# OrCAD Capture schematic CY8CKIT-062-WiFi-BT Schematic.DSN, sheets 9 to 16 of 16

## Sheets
9 10. PSoC 6 Signals: size A4
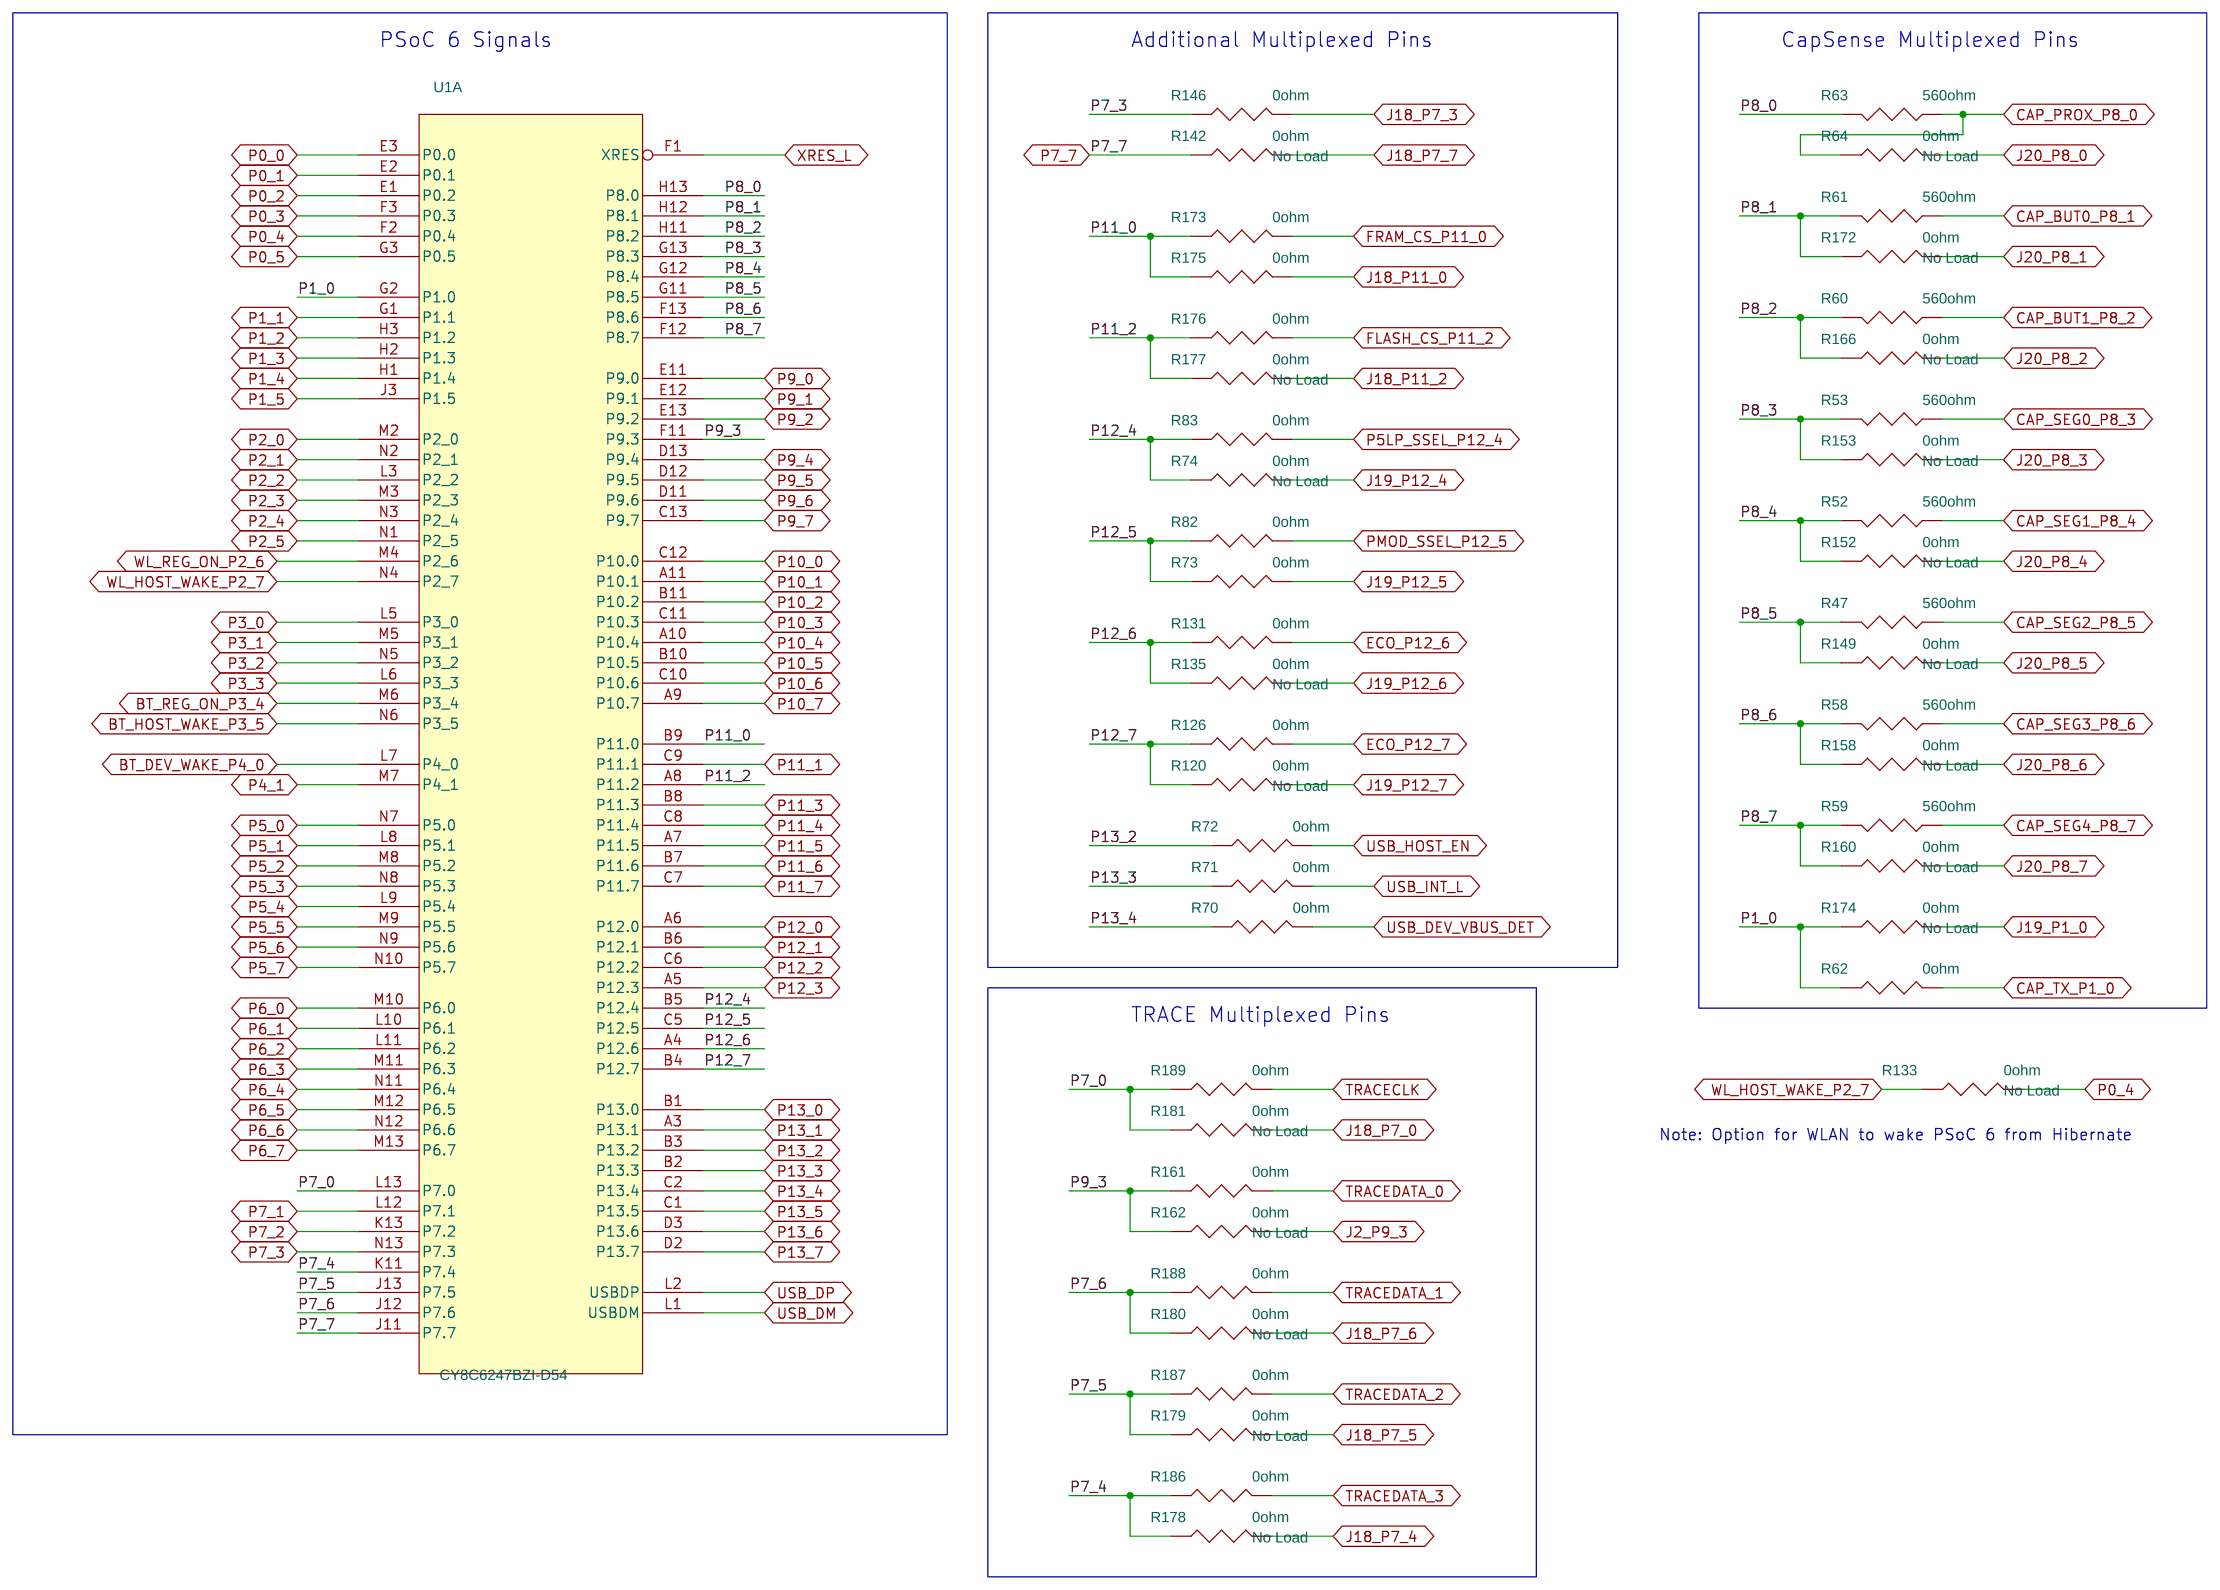
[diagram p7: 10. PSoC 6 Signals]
10 11. On-board Peripherals: size A4
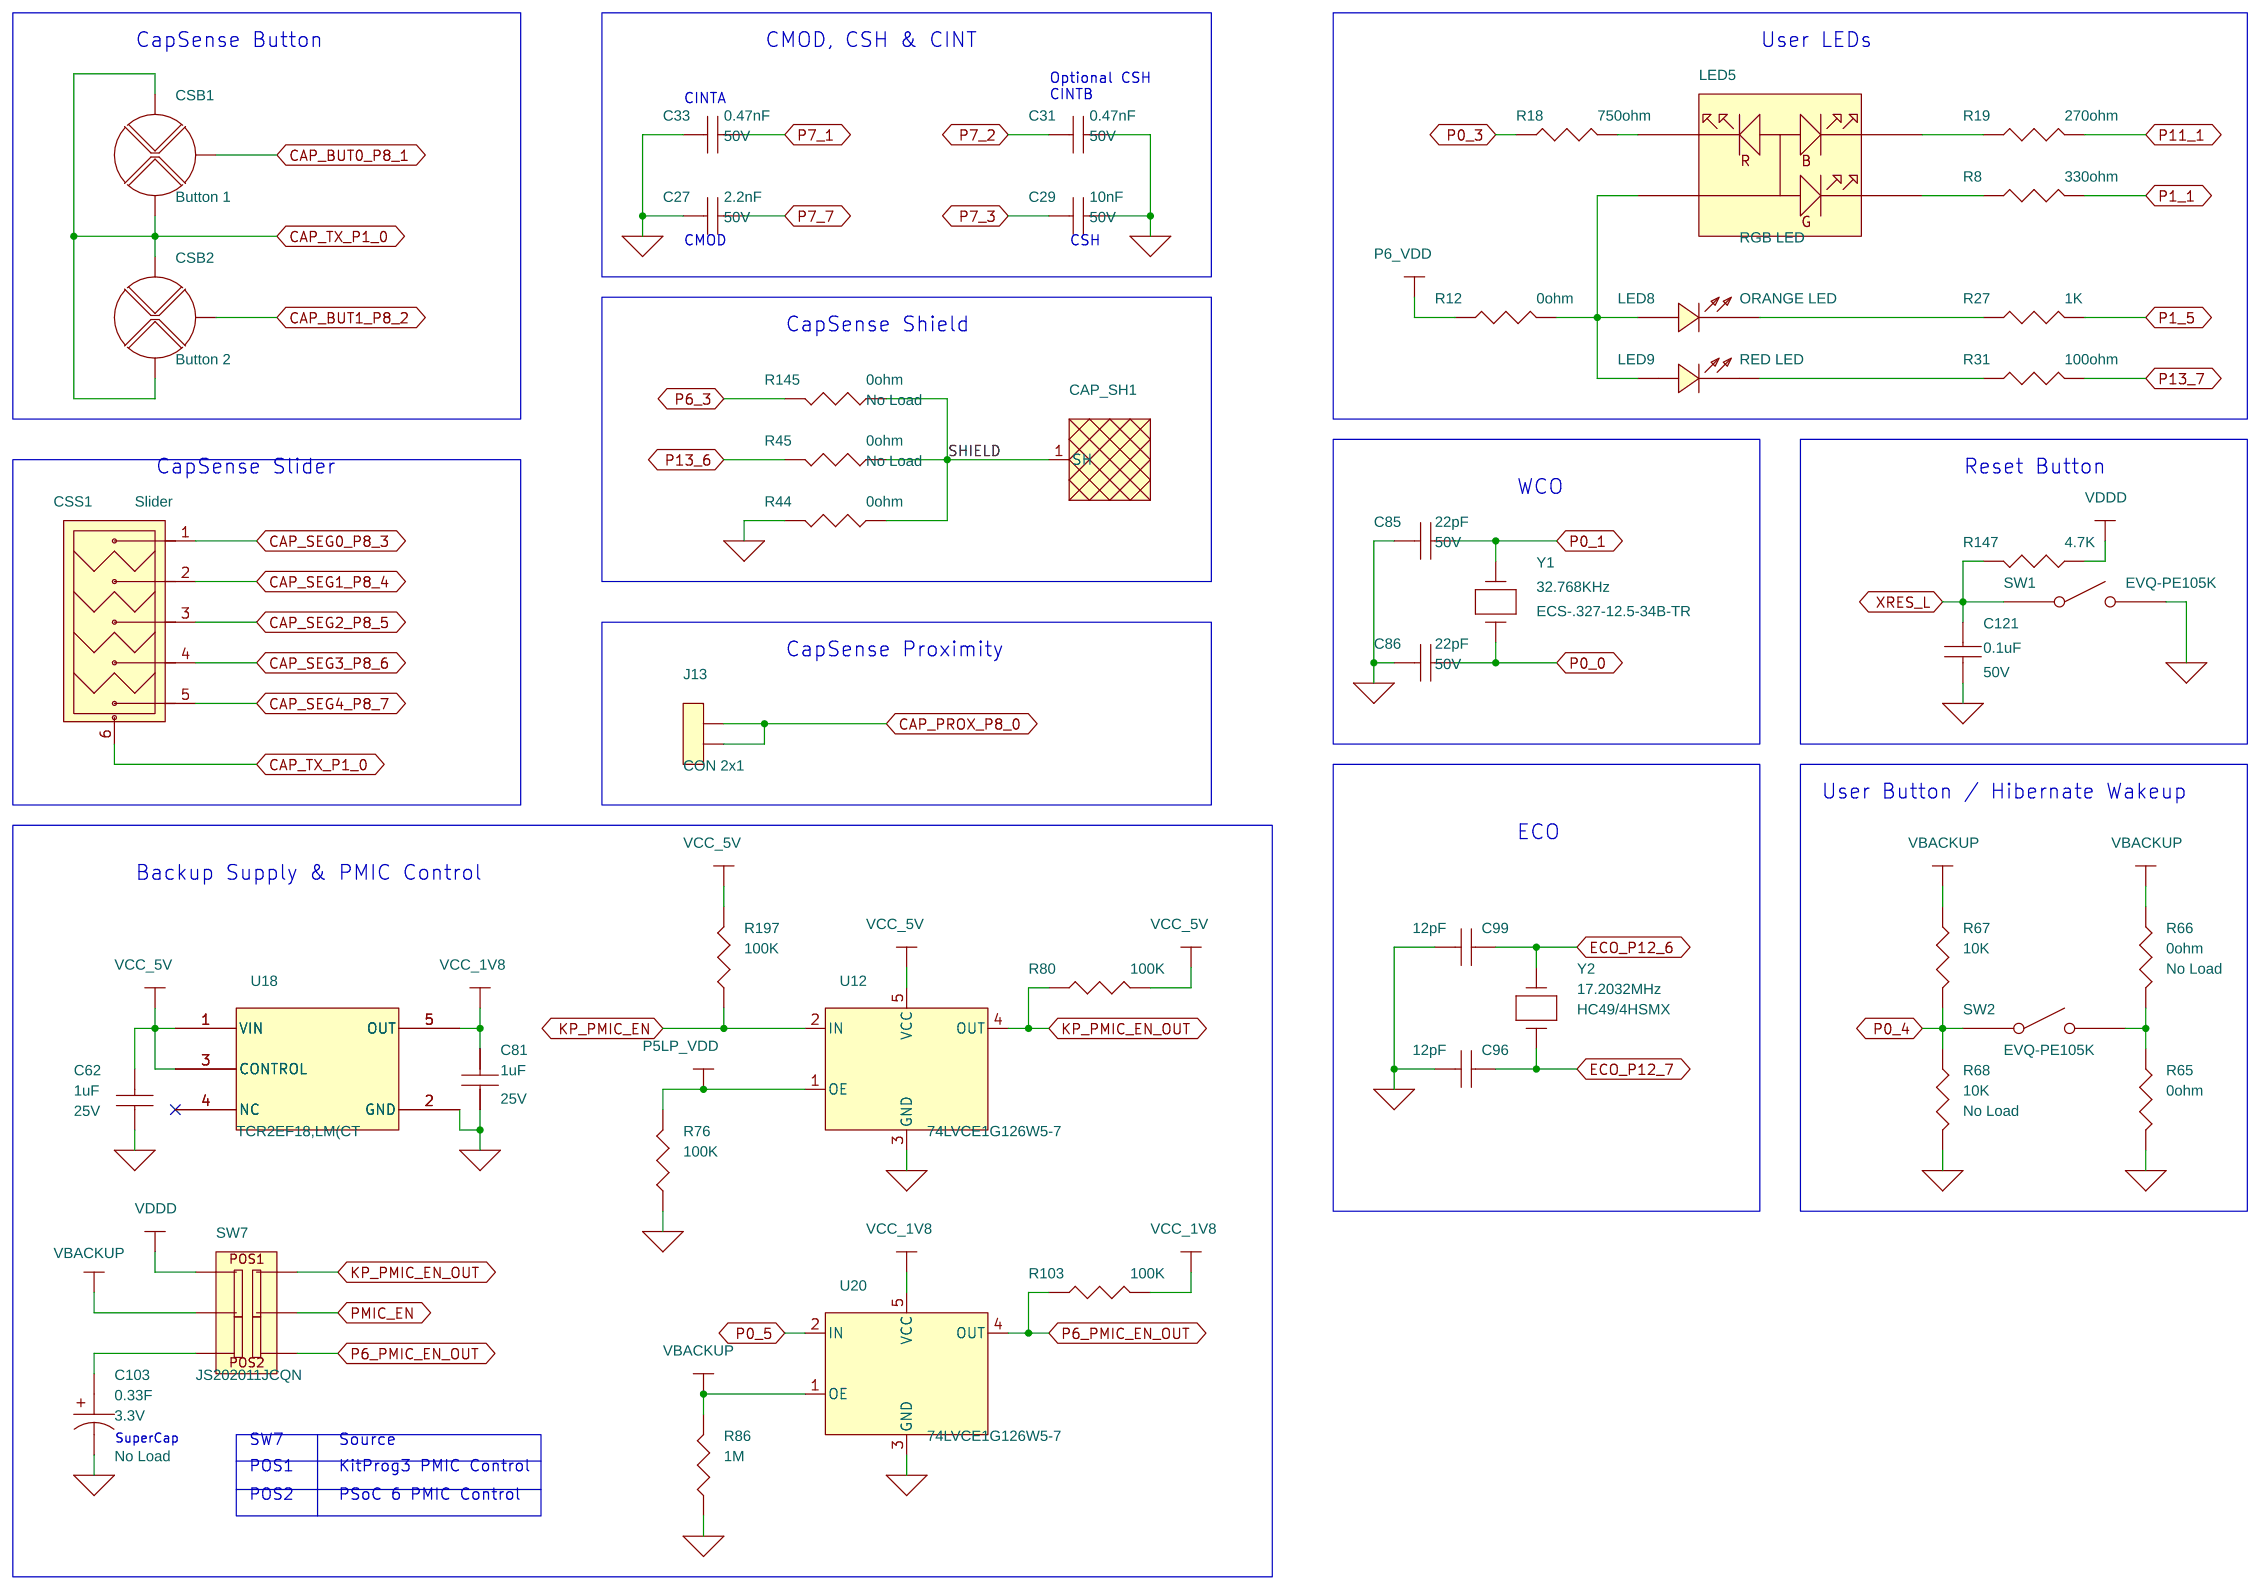
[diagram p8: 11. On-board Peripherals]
11 12. Expansion headers & memory: size A4
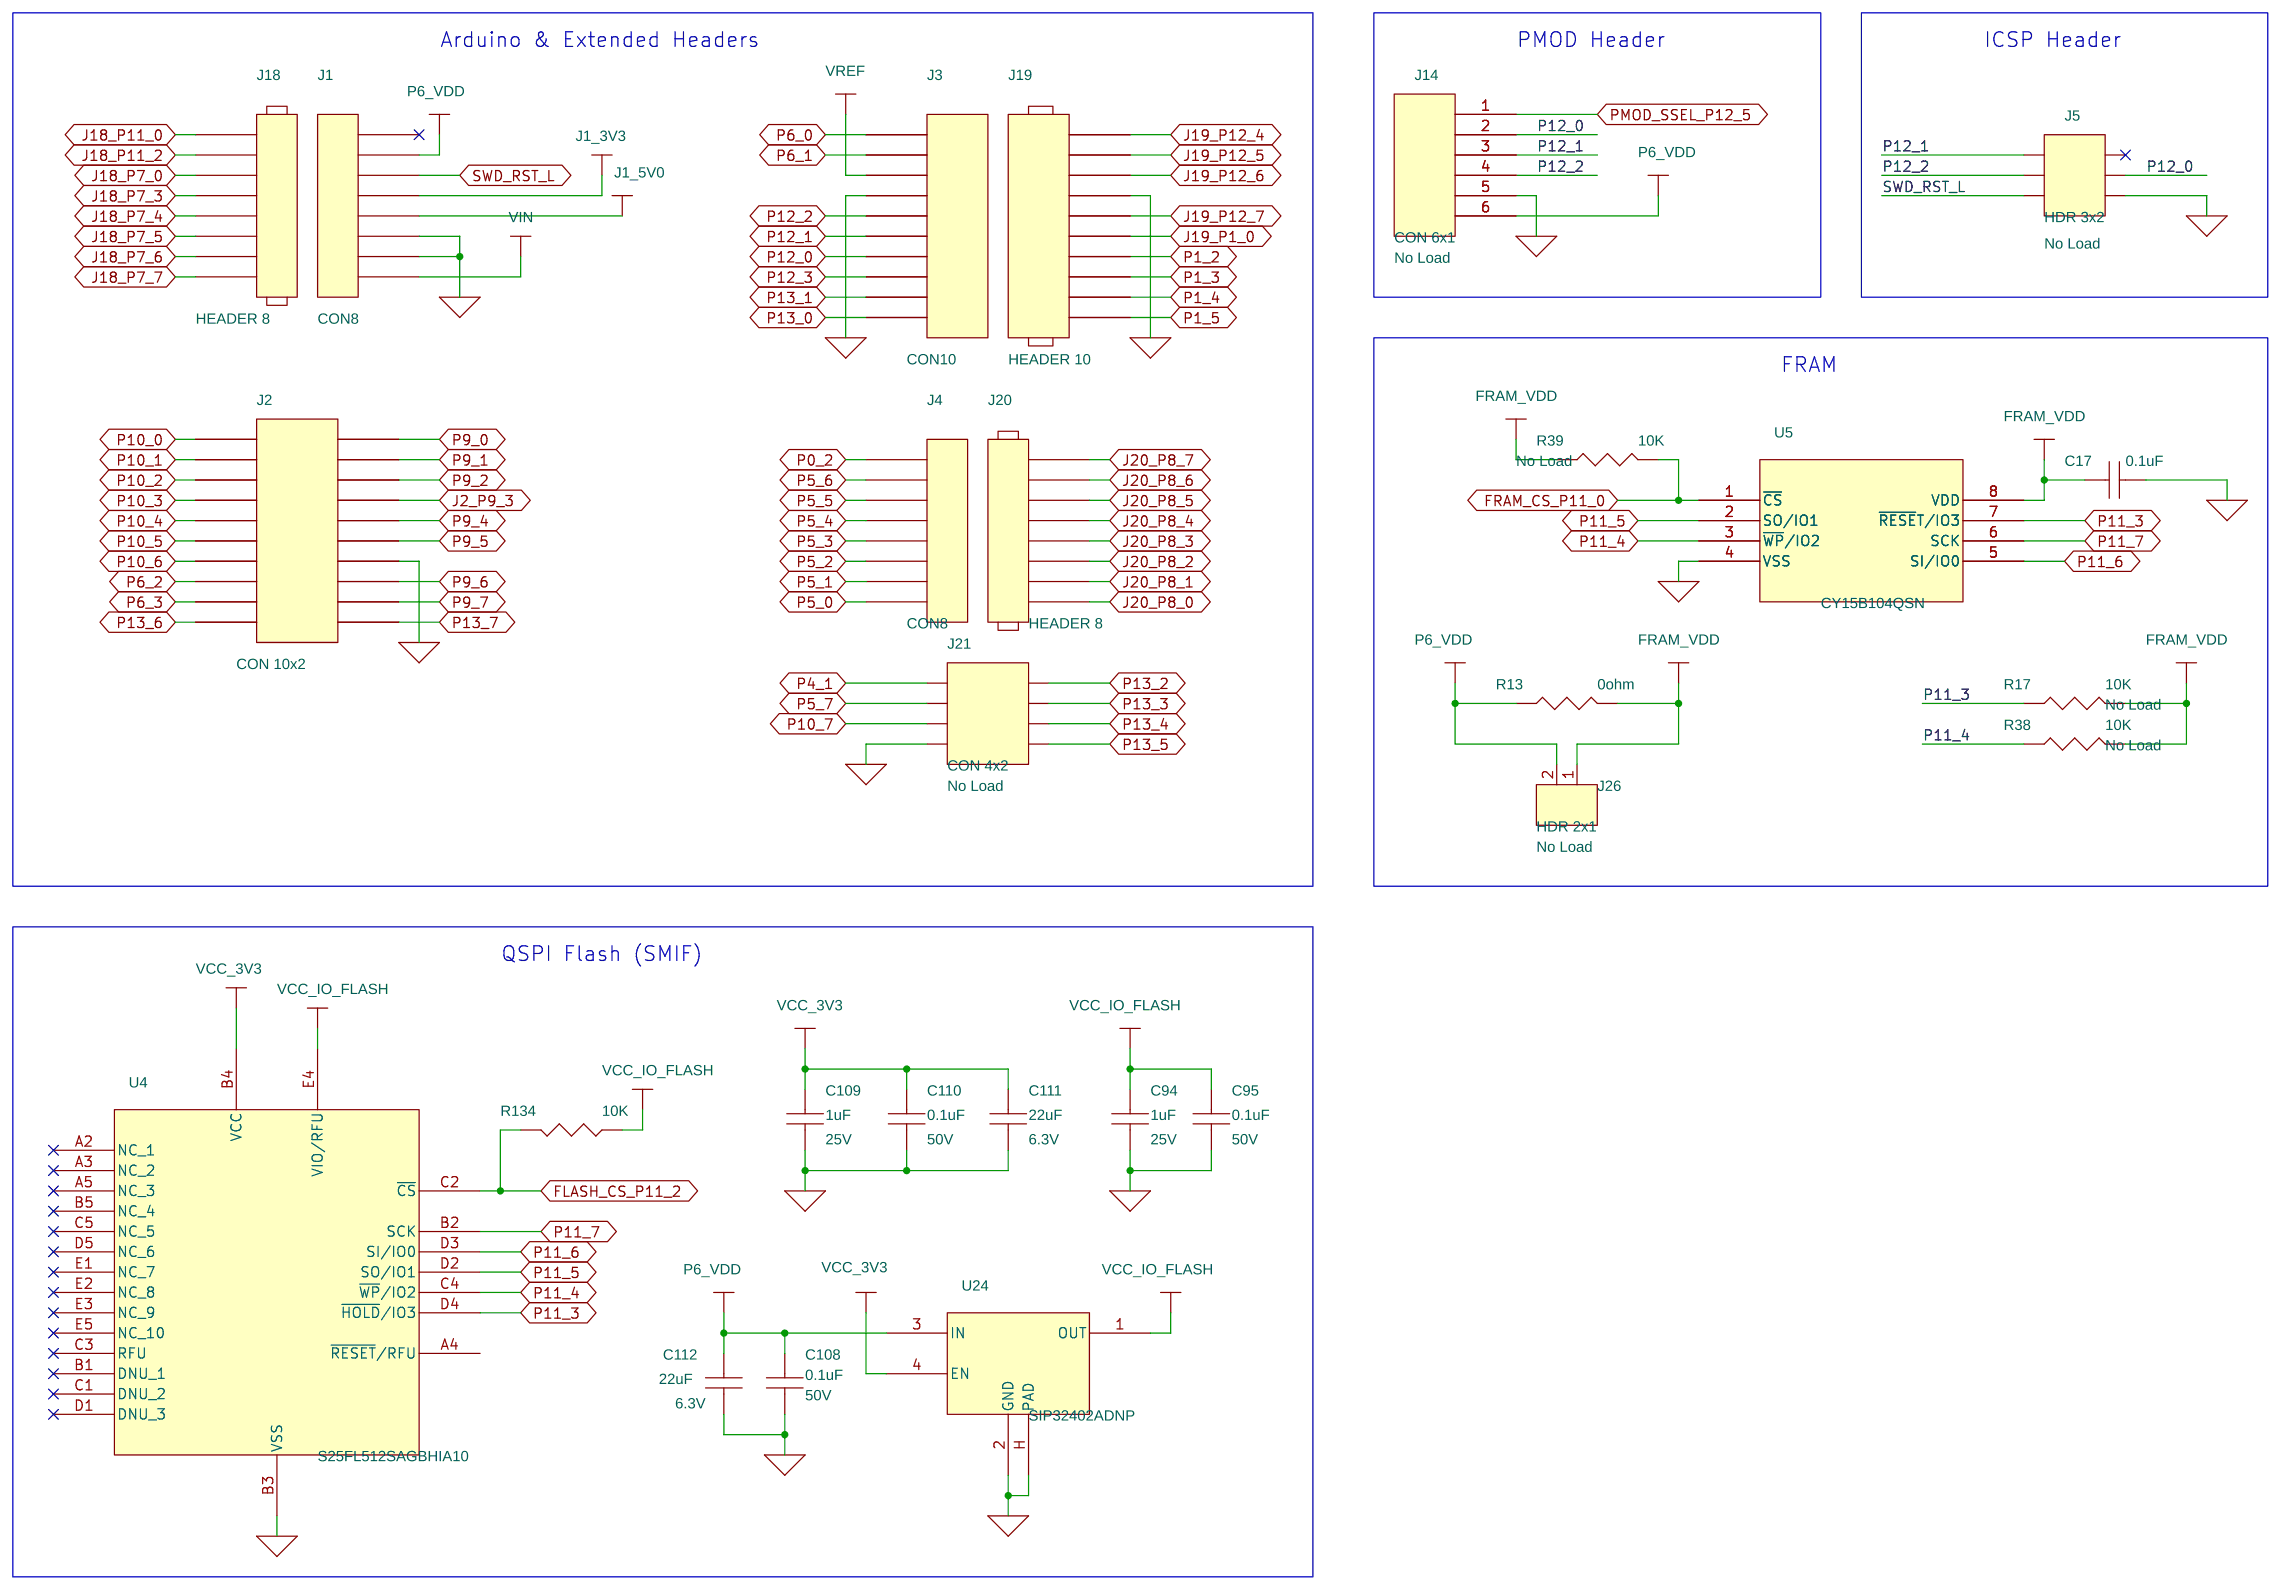
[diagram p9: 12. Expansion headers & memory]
12 13. USB host and device: size A4
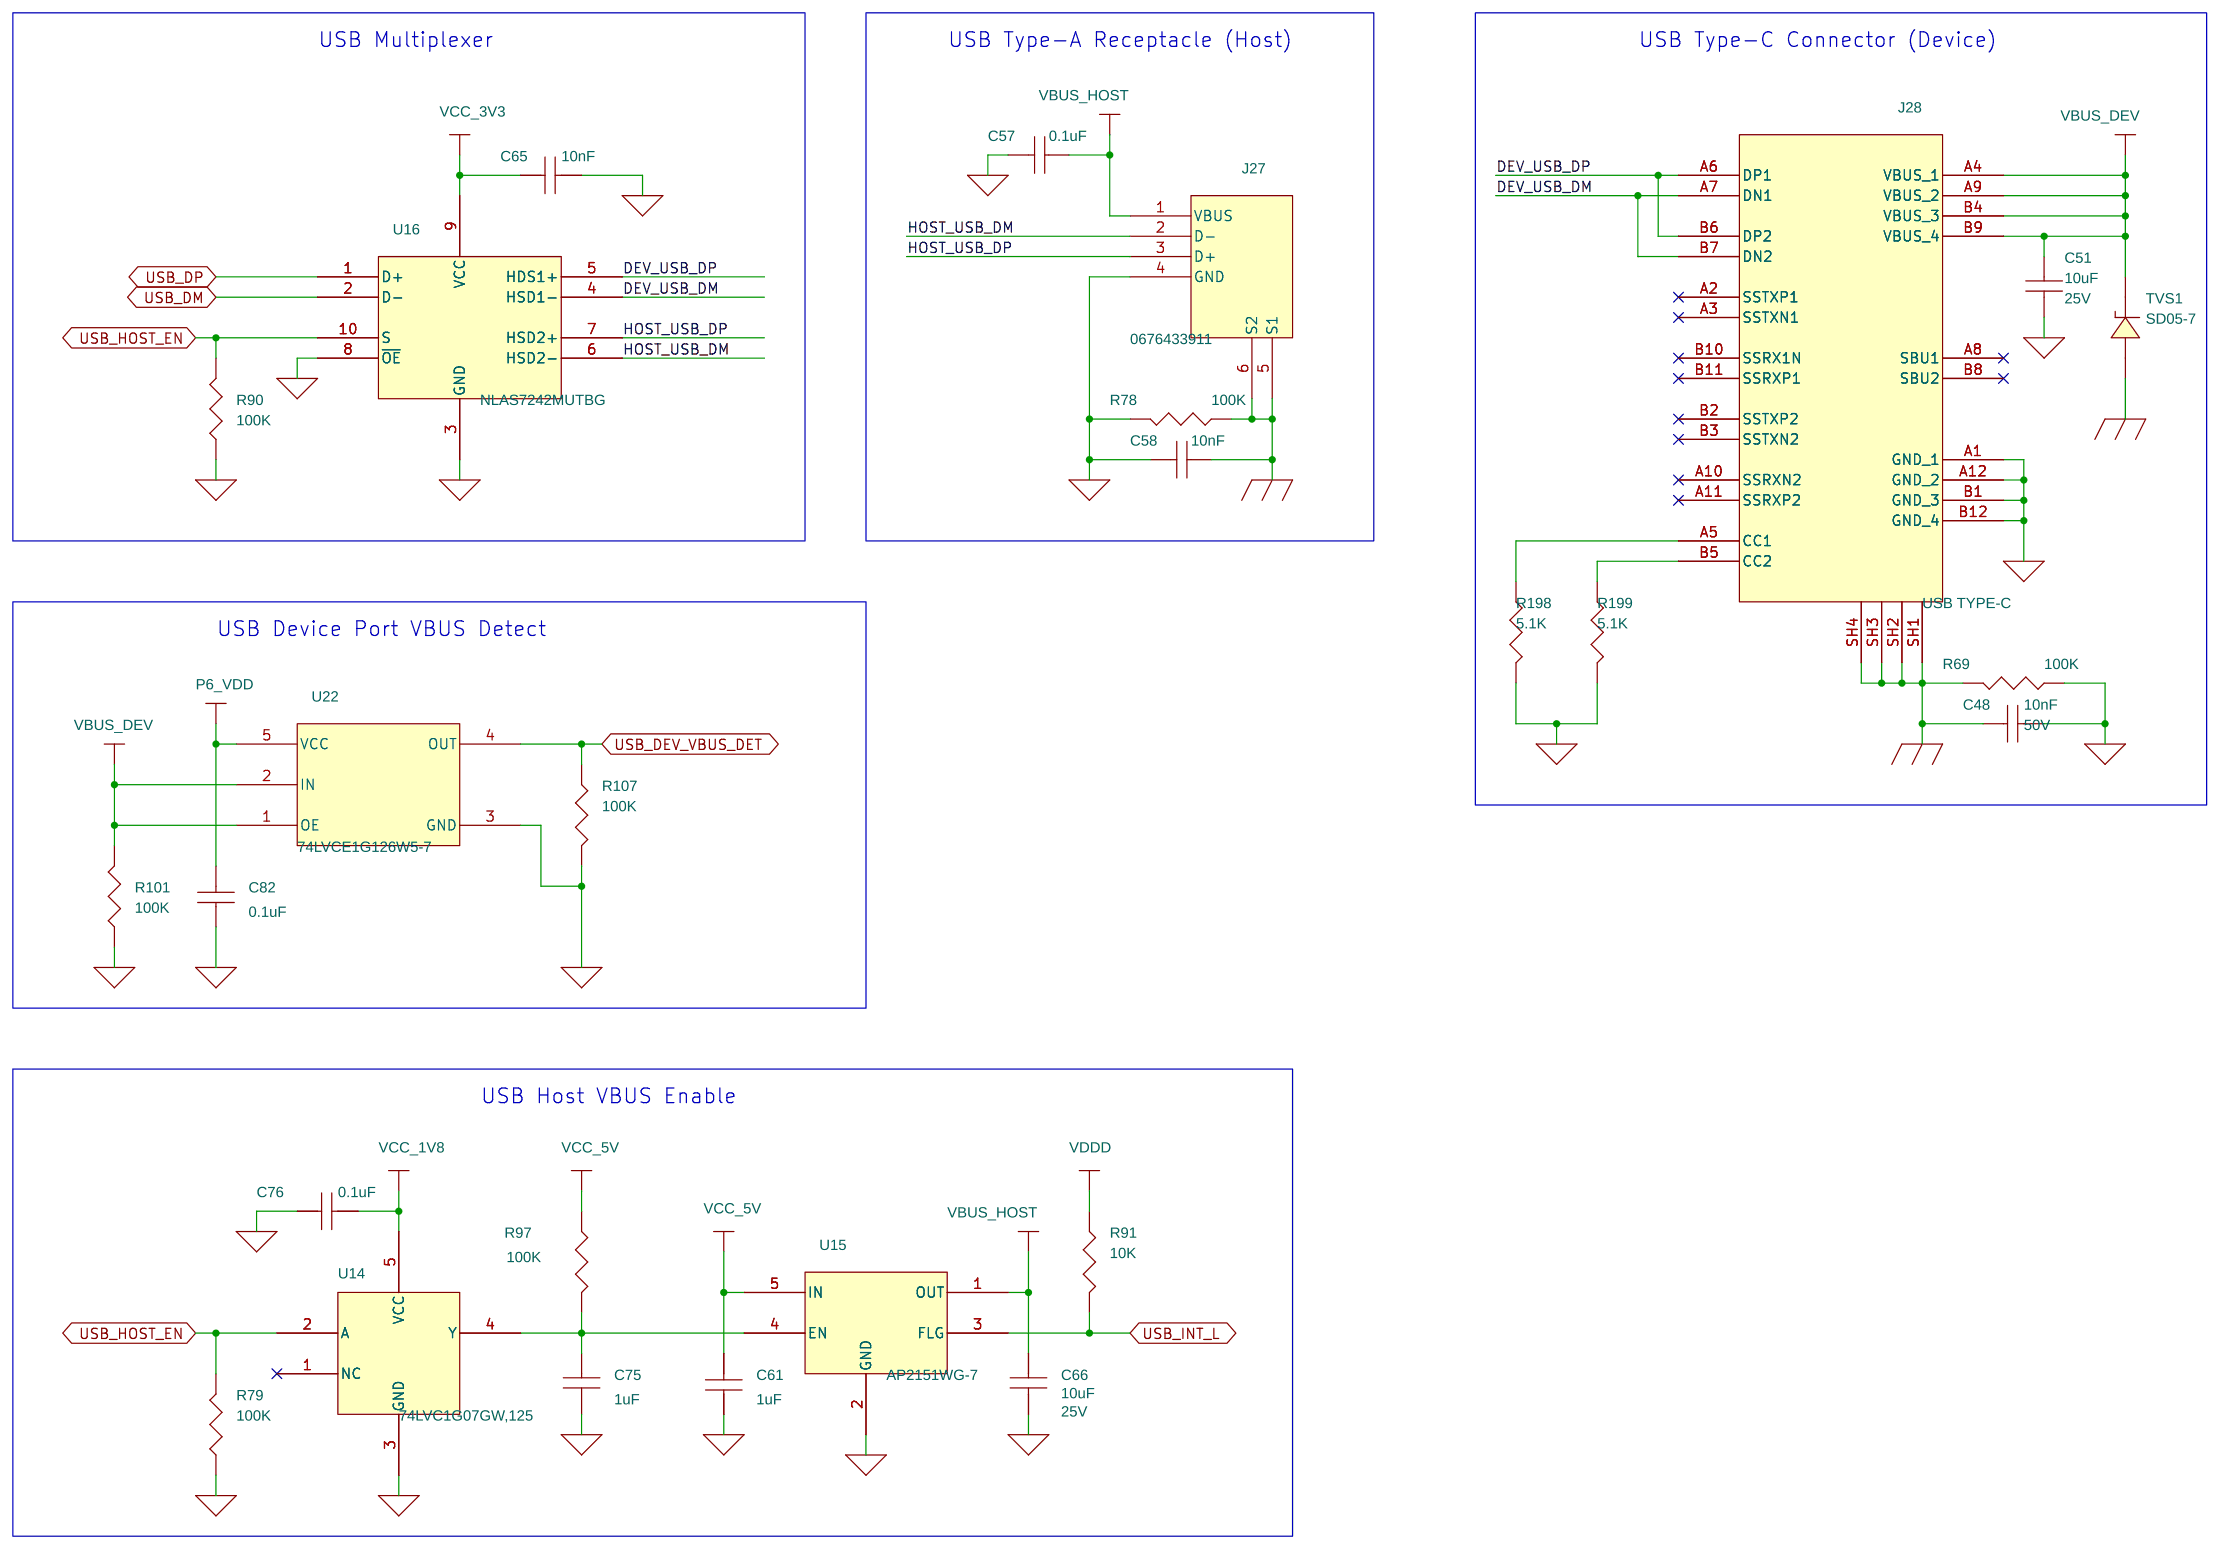
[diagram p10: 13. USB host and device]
13 14. Wi Fi module: size A4
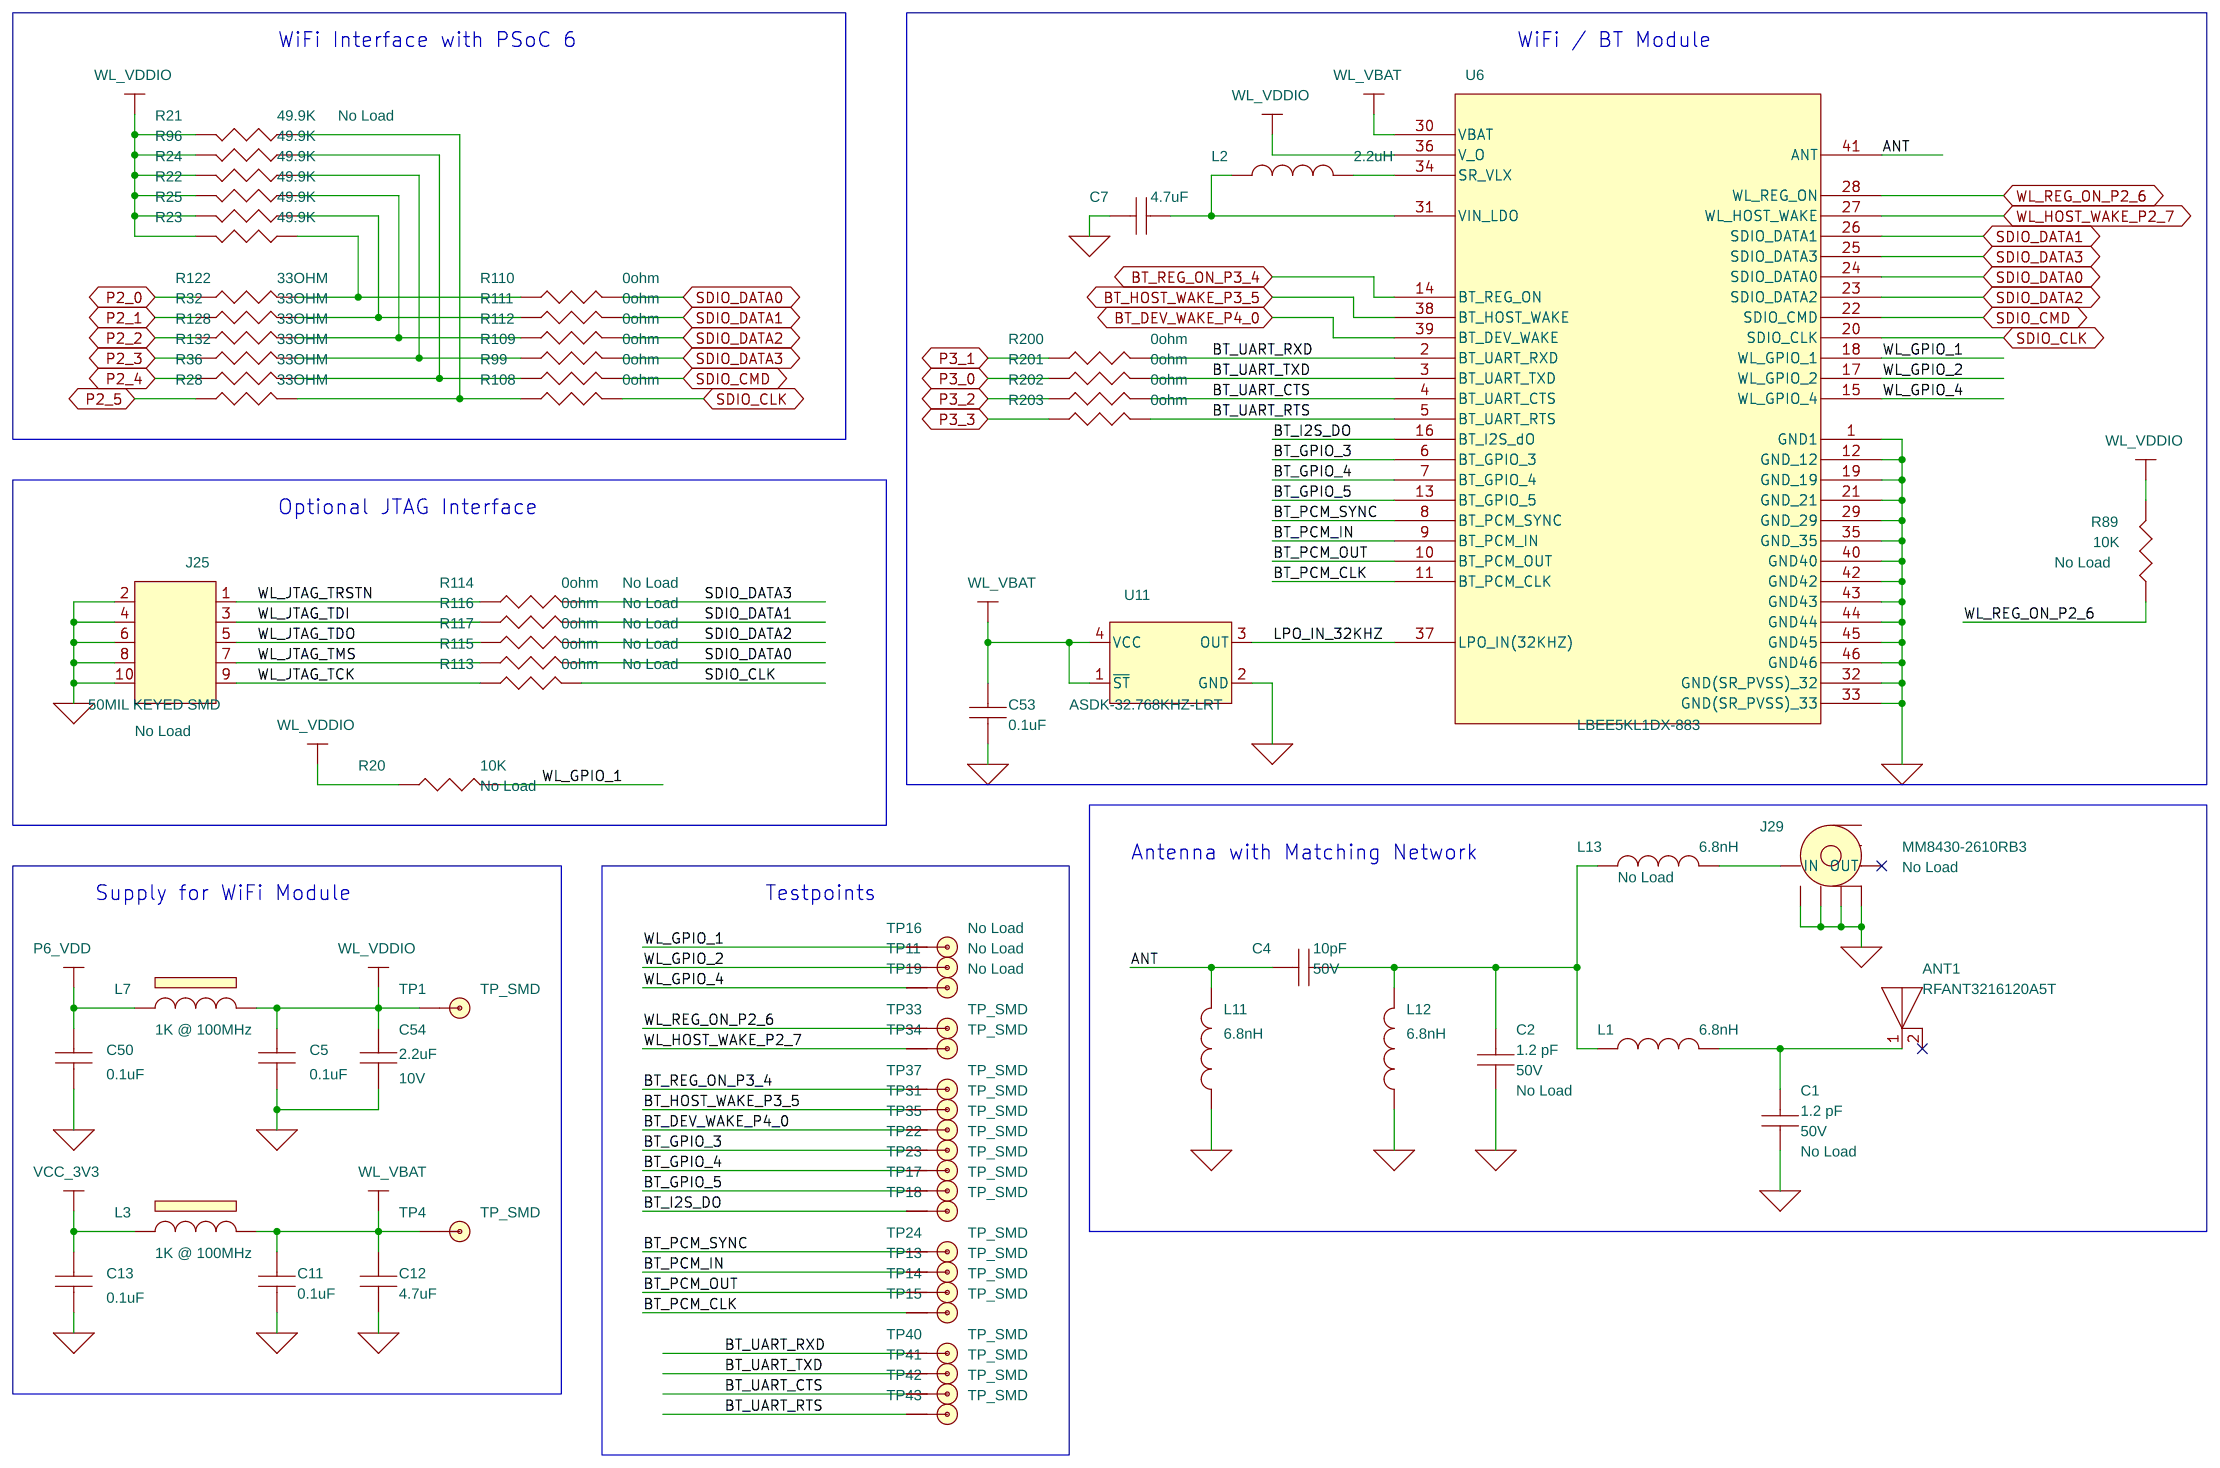
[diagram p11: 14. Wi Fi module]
14 15. Accessories
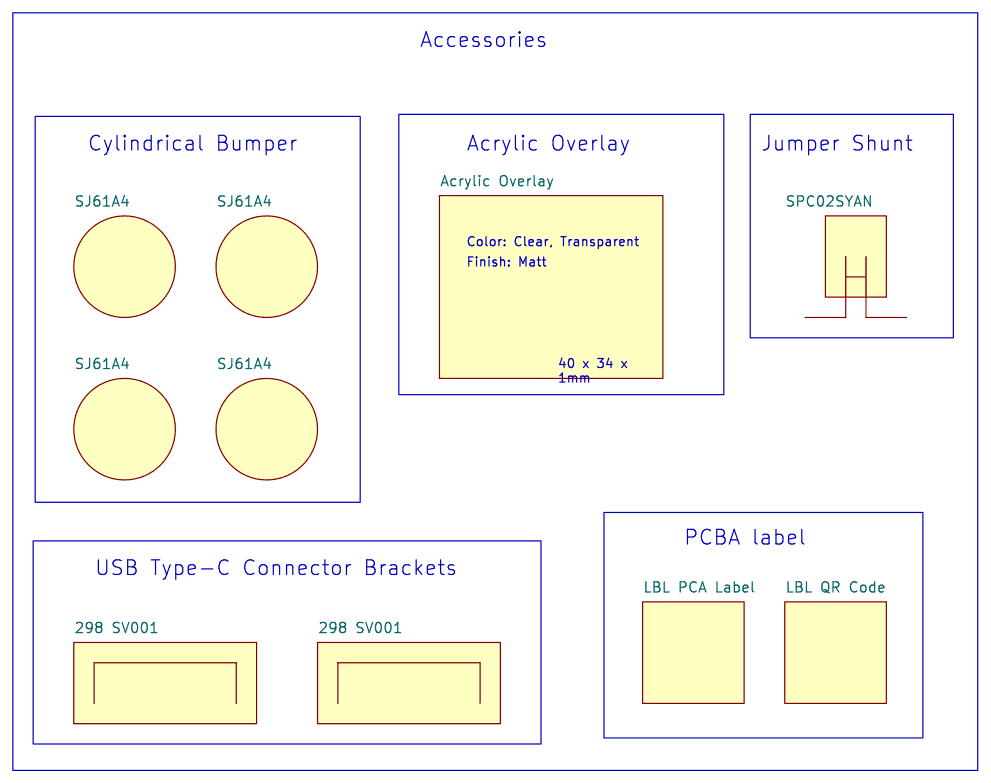
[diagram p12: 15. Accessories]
15 16. Revision History
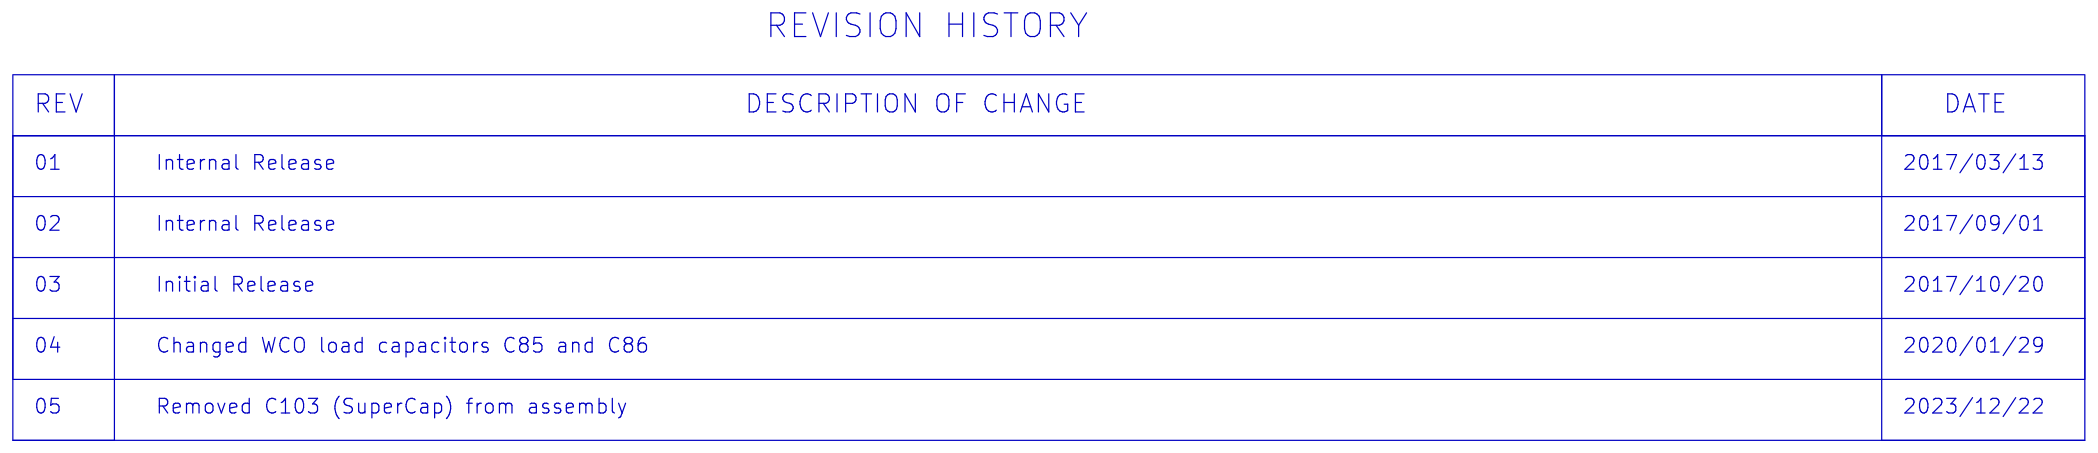
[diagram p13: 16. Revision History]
16 03. 5V Buck/Boost Regulator: size A4
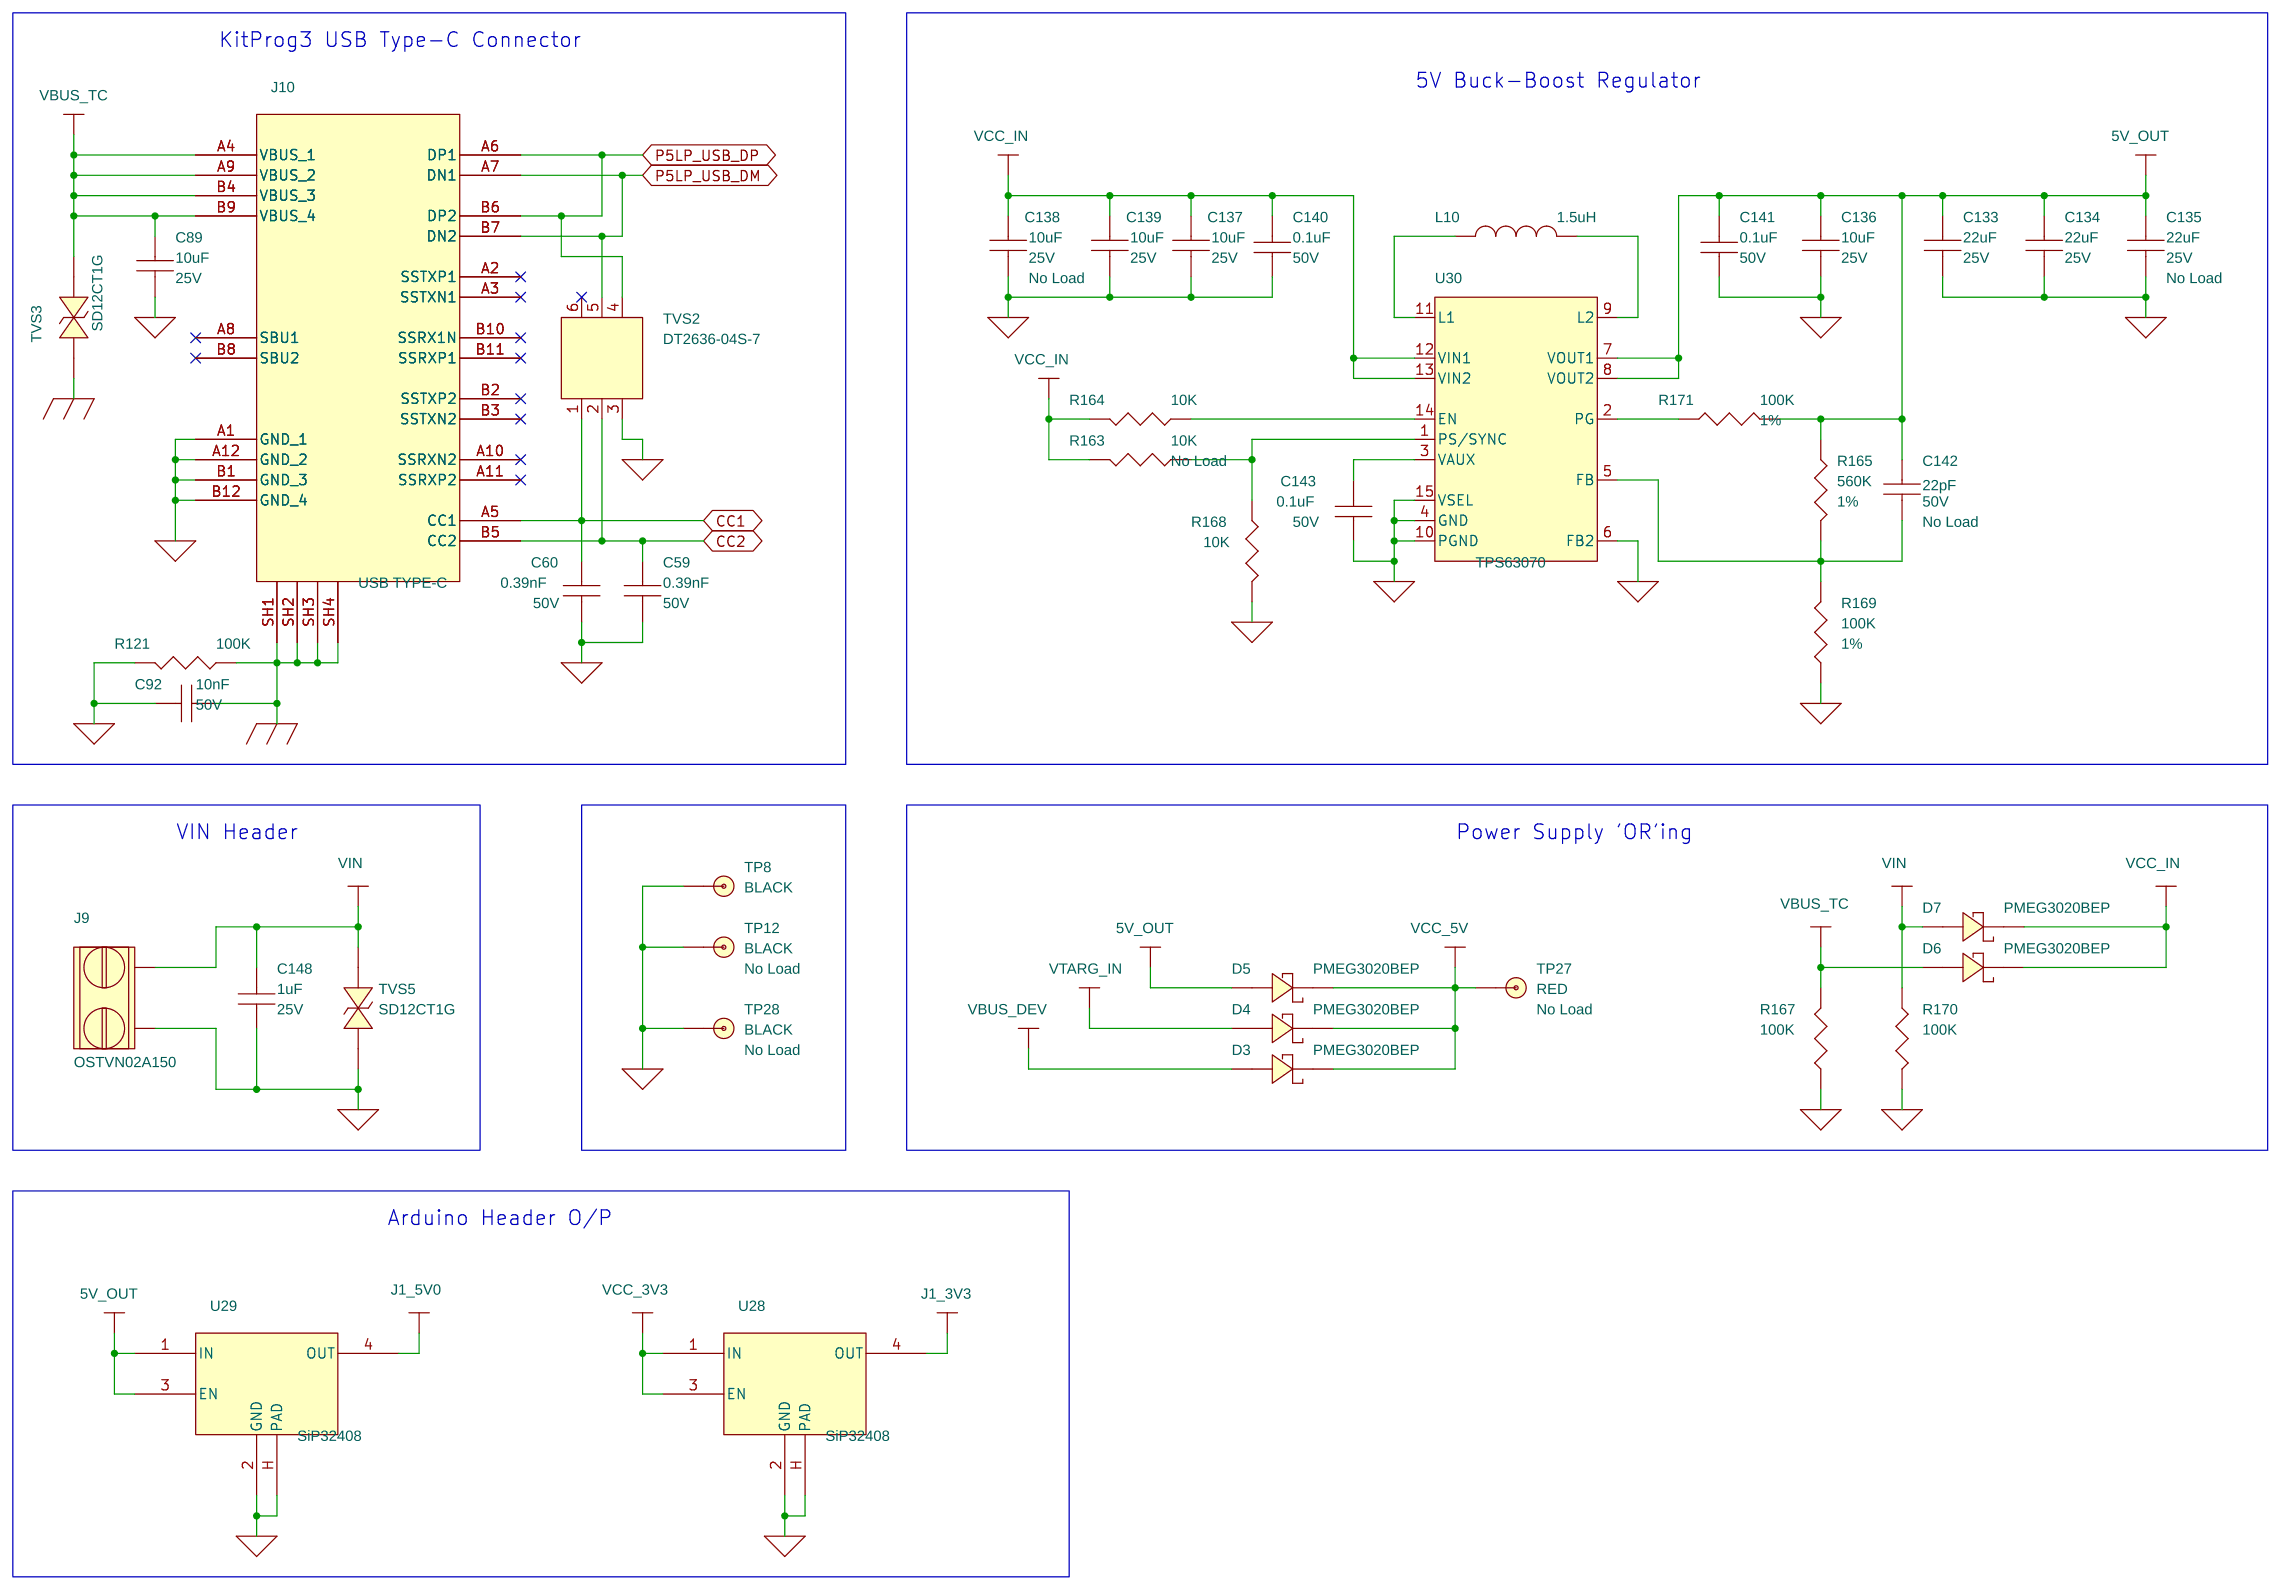
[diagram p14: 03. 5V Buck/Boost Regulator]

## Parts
sheet 03. 5V Buck/Boost Regulator
C59  0.39nF  [CAPC1005X55M_B]
C60  0.39nF  [CAPC1005X55M_B]
C89  10uF  [CAPC2012X140M]
C92  10nF  [CAPC1005X55M_C]
C133  22uF  [CAPC2012X140M]
C134  22uF  [CAPC2012X140M]
C135  22uF  [CAPC2012X140M]
C136  10uF  [CAPC1608X90M]
C137  10uF  [CAPC1608X90M]
C138  10uF  [CAPC2012X140M]
C139  10uF  [CAPC2012X140M]
C140  0.1uF  [CAPC1005X55M_C]
C141  0.1uF  [CAPC1005X55M_C]
C142  22pF  [CAPC1005X55M]
C143  0.1uF  [CAPC1005X55M_C]
C148  1uF  [CAPC1005X55M_C]
D3  PMEG3020BEP  [SODFL4725X110M]
D4  PMEG3020BEP  [SODFL4725X110M]
D5  PMEG3020BEP  [SODFL4725X110M]
D6  PMEG3020BEP  [SODFL4725X110M]
D7  PMEG3020BEP  [SODFL4725X110M]
J9  OSTVN02A150  [OST_OSTVN02A150]
J10  USB TYPE-C  [jae_dx07s024xj1r1100]
L10  1.5uH  [INDM4242X200M]
R121  100K  [RESC1005X40M_B]
R163  10K  [RESC1005X40M_A]
R164  10K  [RESC1005X40M_A]
R165  560K  [RESC1005X40M]
R167  100K  [RESC1005X40M_B]
R168  10K  [RESC1005X40M_A]
R169  100K  [RESC1005X40M]
R170  100K  [RESC1005X40M_B]
R171  100K  [RESC1005X40M_A]
TP8  BLACK  [KEYSTONE_5000]
TP12  BLACK  [KEYSTONE_5000]
TP27  RED  [KEYSTONE_5000]
TP28  BLACK  [KEYSTONE_5000]
TVS2  DT2636-04S-7  [SOT65P210X110-6M]
TVS3  SD12CT1G  [sod2513x120m_12_di]
TVS5  SD12CT1G  [sod2513x120m_12_di]
U28  SiP32408  [TDFN50P160X120X60-5M]
U29  SiP32408  [TDFN50P160X120X60-5M]
U30  TPS63070  [qfn50p250x300x100-15m_NOFID]
sheet 09. PSoC 6 Power
U1  CY8C6247BZI-D54  [BGA124C65P13X13_900X900X100]  (sections A,B)
sheet 10. PSoC 6 Signals
R47  560ohm  [RESC1608X55M_A]
R52  560ohm  [RESC1608X55M_A]
R53  560ohm  [RESC1608X55M_A]
R58  560ohm  [RESC1608X55M_A]
R59  560ohm  [RESC1608X55M_A]
R60  560ohm  [RESC1608X55M_A]
R61  560ohm  [RESC1608X55M_A]
R62  0ohm  [RESC1608X55M_A]
R63  560ohm  [RESC1608X55M_A]
R64  0ohm  [RESC1608X55M_A]
R70  0ohm  [RESC1608X55M_A]
R71  0ohm  [RESC1608X55M_A]
R72  0ohm  [RESC1608X55M_A]
R73  0ohm  [RESC1608X55M_A]
R74  0ohm  [RESC1608X55M_A]
R82  0ohm  [RESC1608X55M_A]
R83  0ohm  [RESC1608X55M_A]
R120  0ohm  [RESC1608X55M_A]
R126  0ohm  [RESC1608X55M_A]
R131  0ohm  [RESC1608X55M_A]
R133  0ohm  [RESC1005X40M]
R135  0ohm  [RESC1608X55M_A]
R142  0ohm  [RESC1608X55M_A]
R146  0ohm  [RESC1608X55M_A]
R149  0ohm  [RESC1608X55M_A]
R152  0ohm  [RESC1608X55M_A]
R153  0ohm  [RESC1608X55M_A]
R158  0ohm  [RESC1608X55M_A]
R160  0ohm  [RESC1608X55M_A]
R161  0ohm  [RESC1608X55M_A]
R162  0ohm  [RESC1608X55M_A]
R166  0ohm  [RESC1608X55M_A]
R172  0ohm  [RESC1608X55M_A]
R173  0ohm  [RESC1608X55M_A]
R174  0ohm  [RESC1608X55M_A]
R175  0ohm  [RESC1608X55M_A]
R176  0ohm  [RESC1608X55M_A]
R177  0ohm  [RESC1608X55M_A]
R178  0ohm  [RESC1608X55M_A]
R179  0ohm  [RESC1608X55M_A]
R180  0ohm  [RESC1608X55M_A]
R181  0ohm  [RESC1608X55M_A]
R186  0ohm  [RESC1608X55M_A]
R187  0ohm  [RESC1608X55M_A]
R188  0ohm  [RESC1608X55M_A]
R189  0ohm  [RESC1608X55M_A]
sheet 11. On-board Peripherals
C27  2.2nF  [CAPC2012X70M]
C29  10nF  [CAPC2012X95M_A]
C31  0.47nF  [CAPC2012X70M]
C33  0.47nF  [CAPC2012X70M]
C62  1uF  [CAPC1005X55M_D]
C81  1uF  [CAPC1005X55M_D]
C85  22pF  [CAPC1005X55M_D]
C86  22pF  [CAPC1005X55M_D]
C96  12pF  [CAPC1005X55M_D]
C99  12pF  [CAPC1005X55M_D]
C103  0.33F  [CAP_DSK-3R3H334T-HL]
C121  0.1uF  [CAPC1005X55M_C]
CAP_SH1  CAP_SHIELD  [CAP_SH1]
CSB1  Button 1  [CSB_10MM_3SEG]
CSB2  Button 2  [CSB_10MM_3SEG]
CSS1  Slider  [CSS_L5S_4X12_1P4_MUTUAL_CYPS]
J13  CON 2x1  [SAMTEC_BCS-101-L-S-HE]
LED5  RGB LED  [LED_AAA3528LSEEZGKQBKS]
LED8  ORANGE LED  [LEDC2012X120M]
LED9  RED LED  [LEDC2012X120M]
R8  330ohm  [RESC1005X40M_B]
R12  0ohm  [RESC1608X55M_A]
R18  750ohm  [RESC1005X40M_B]
R19  270ohm  [RESC1005X40M_B]
R27  1K  [RESC1005X40M_B]
R31  100ohm  [RESC1005X40M_B]
R44  0ohm  [RESC1608X55M_A]
R45  0ohm  [RESC1608X55M_A]
R65  0ohm  [RESC1608X55M_A]
R66  0ohm  [RESC1608X55M_A]
R67  10K  [RESC1005X40M_A]
R68  10K  [RESC1005X40M_A]
R76  100K  [RESC1005X40M_B]
R80  100K  [RESC1005X40M_B]
R86  1M  [RESC1005X40M_B]
R103  100K  [RESC1005X40M_B]
R145  0ohm  [RESC1608X55M_A]
R147  4.7K  [RESC1005X40M_A]
R197  100K  [RESC1005X40M_B]
SW1  EVQ-PE105K  [SW_EVQ-PE105K]
SW2  EVQ-PE105K  [SW_EVQ-PE105K]
SW7  JS202011JCQN  [SW_JS202011JCQN]
U12  74LVCE1G126W5-7  [SOT95P280X145-5M]
U18  TCR2EF18,LM(CT  [SOT95P275X140-5M]
U20  74LVCE1G126W5-7  [SOT95P280X145-5M]
Y1  32.768KHz  [XTAL320X150X90N_ECS]
Y2  17.2032MHz  [XTL-11-5X4-8MM_DAB]
sheet 12. Expansion headers & memory
C17  0.1uF  [CAPC1005X55M_C]
C94  1uF  [CAPC1005X55M_D]
C95  0.1uF  [CAPC1005X55M_C]
C108  0.1uF  [CAPC1005X55M_C]
C109  1uF  [CAPC1005X55M_D]
C110  0.1uF  [CAPC1005X55M_C]
C111  22uF  [CAPC1608X90M]
C112  22uF  [CAPC1608X90M]
J1  CON8  [SULLINS_PPPC081LFBN-RC]
J2  CON 10x2  [SULLINS_PPPC102LFBN-R_FLIP]
J3  CON10  [SULLINS_PPPC101LFBN-RC]
J4  CON8  [SULLINS_PPPC081LFBN-RC]
J5  HDR 3x2  [SULLINS_PPPC032LFBN-RC_flip]
J14  CON 6x1  [SULLINS_PPPC061LGBN-RC_FLIP]
J18  HEADER 8  [SULLINS_PBC08SAAN]
J19  HEADER 10  [SULLINS_PBC10SAAN]
J20  HEADER 8  [SULLINS_PBC08SAAN]
J21  CON 4x2  [sullins_PPPC042LFBN-RC_FLIP]
J26  HDR 2x1  [3M_961102-6404-AR]
R13  0ohm  [RESC1608X55M_A]
R17  10K  [RESC1005X40M_A]
R38  10K  [RESC1005X40M_A]
R39  10K  [RESC1005X40M_A]
R134  10K  [RESC1005X40M]
U4  S25FL512SAGBHIA10  [BGA24C100P5X5_600X800X120]
U5  CY15B104QSN  [soic127p800x203-8m]
U24  SIP32402ADNP  [TDFN50P160X120X60-5M]
sheet 13. USB host and device
C48  10nF  [CAPC1005X55M_C]
C51  10uF  [CAPC2012X140M]
C57  0.1uF  [CAPC1005X55M_C]
C58  10nF  [CAPC1005X55M_C]
C61  1uF  [CAPC1005X55M_D]
C65  10nF  [CAPC1005X55M_C]
C66  10uF  [CAPC2012X100M]
C75  1uF  [CAPC1005X55M_D]
C76  0.1uF  [CAPC1005X55M_C]
C82  0.1uF  [CAPC1005X55M_C]
J27  0676433911  [MOLEX_676433911]
J28  USB TYPE-C  [jae_dx07s024xj1r1100]
R69  100K  [RESC1005X40M_B]
R78  100K  [RESC1005X40M_B]
R79  100K  [RESC1005X40M_B]
R90  100K  [RESC1005X40M_A]
R91  10K  [RESC1005X40M_A]
R97  100K  [RESC1005X40M_B]
R101  100K  [RESC1005X40M_A]
R107  100K  [RESC1005X40M_B]
R198  5.1K  [RESC1005X40M_A]
R199  5.1K  [RESC1005X40M_A]
TVS1  SD05-7  [SOD2513X120M_DI]
U14  74LVC1G07GW,125  [TSSOP65P212X110-5M]
U15  AP2151WG-7  [SOT95P285X140-5M]
U16  NLAS7242MUTBG  [QFN40P140X180X60-10M]
U22  74LVCE1G126W5-7  [SOT95P280X145-5M]
sheet 14. Wi Fi module
ANT1  RFANT3216120A5T  [ANTENNA_RFANT3216120A5T]
C1  1.2 pF  [CAPC1005X61M]
C2  1.2 pF  [CAPC1005X61M]
C4  10pF  [CAPC1005X61M]
C5  0.1uF  [CAPC1005X55M_C]
C7  4.7uF  [CAPC1608X90M]
C11  0.1uF  [CAPC1005X55M_C]
C12  4.7uF  [CAPC1608X90M]
C13  0.1uF  [CAPC1005X55M_C]
C50  0.1uF  [CAPC1005X55M_C]
C53  0.1uF  [CAPC1005X55M_C]
C54  2.2uF  [CAPC1005X55M]
J25  50MIL KEYED SMD  [SAMTEC_FTSH-105-01-L-DV-K]
J29  MM8430-2610RB3  [RF_SW_MUR_MM8430-2610B]
L1  6.8nH  [INDC1005X60M]
L2  2.2uH  [INDC2016X100M]
L3  1K @ 100MHz  [INDC2012X105M]
L7  1K @ 100MHz  [INDC2012X105M]
L11  6.8nH  [INDC1005X60M]
L12  6.8nH  [INDC1005X60M]
L13  6.8nH  [INDC1005X60M]
R20  10K  [RESC1005X40M_A]
R21  49.9K  [RESC1005X40M_B]
R22  49.9K  [RESC1005X40M_B]
R23  49.9K  [RESC1005X40M_B]
R24  49.9K  [RESC1005X40M_B]
R25  49.9K  [RESC1005X40M_B]
R28  33OHM  [RESC1005X40M_B]
R32  33OHM  [RESC1005X40M_B]
R36  33OHM  [RESC1005X40M_B]
R89  10K  [RESC1005X40M_A]
R96  49.9K  [RESC1005X40M_B]
R99  0ohm  [RESC1005X40M]
R108  0ohm  [RESC1005X40M]
R109  0ohm  [RESC1005X40M]
R110  0ohm  [RESC1005X40M]
R111  0ohm  [RESC1005X40M]
R112  0ohm  [RESC1005X40M]
R113  0ohm  [RESC1005X40M]
R114  0ohm  [RESC1005X40M]
R115  0ohm  [RESC1005X40M]
R116  0ohm  [RESC1005X40M]
R117  0ohm  [RESC1005X40M]
R122  33OHM  [RESC1005X40M_B]
R128  33OHM  [RESC1005X40M_B]
R132  33OHM  [RESC1005X40M_B]
R200  0ohm  [RESC1005X40M]
R201  0ohm  [RESC1005X40M]
R202  0ohm  [RESC1005X40M]
R203  0ohm  [RESC1005X40M]
TP1  TP_SMD  [TP127D033]
TP4  TP_SMD  [TP127D033]
TP11  RED  [KEYSTONE_5000]
TP13  TP_SMD  [TP102C]
TP14  TP_SMD  [TP102C]
TP15  TP_SMD  [TP102C]
TP16  RED  [KEYSTONE_5000]
TP17  TP_SMD  [TP102C]
TP18  TP_SMD  [TP102C]
TP19  RED  [KEYSTONE_5000]
TP22  TP_SMD  [TP102C]
TP23  TP_SMD  [TP102C]
TP24  TP_SMD  [TP102C]
TP31  TP_SMD  [TP102C]
TP33  TP_SMD  [TP102C]
TP34  TP_SMD  [TP102C]
TP35  TP_SMD  [TP102C]
TP37  TP_SMD  [TP102C]
TP40  TP_SMD  [TP102C]
TP41  TP_SMD  [TP102C]
TP42  TP_SMD  [TP102C]
TP43  TP_SMD  [TP102C]
U6  LBEE5KL1DX-883  [MODULE_LBEE5KL1DX-TEMP]
U11  ASDK-32.768KHZ-LRT  [OSCCC200X250X90-4M]
sheet 15. Accessories
ACC6  SJ61A4  [-NA-]
ACC7  SJ61A4  [-NA-]
ACC8  Acrylic Overlay  [-NA-]
ACC9  SPC02SYAN  [-NA-]
ACC10  SJ61A4  [-NA-]
ACC11  SJ61A4  [-NA-]
ACC12  LBL PCA Label  [-NA-]
ACC13  LBL QR Code  [-NA-]
ACC14  298 SV001  [-NA-]
ACC15  298 SV001  [-NA-]

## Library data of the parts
C59 C60 = CAPACITOR_NON-POL: CAP, CER, 390PF, 10%, X7R, 50V, 0402; Cy_part#: 510-60487-01; Mfr_Name: Murata Electronics; Mfr_Part#: GRM155R71H391KA01D; Sub_Asm: Power In; Tolerance: 10%; VOLTAGE: 50V
C51 C89 = CAPACITOR_NON-POL: CAP, CER, 10uF, 10%, 25V, X5R, 0805; Cy_part#: 510-60052-01; Mfr_Name: Murata Electronics; Mfr_Part#: GRM21BR61E106KA73L; Sub_Asm: Power In; Tolerance: 10%; VOLTAGE: 25V
C48 C92 = CAPACITOR_NON-POL: CAP, CER, 0.01uF, 10%, X7R, 50V, 0402; Cy_part#: 510-60089-01; Mfr_Name: Murata Electronics; Mfr_Part#: GRM155R71H103KA88D; Mfr_Part_Number: GRM155R71H103KA88D; Sub_Asm: Power In; Tolerance: 10%; VOLTAGE: 50V
C133 C134 = CAPACITOR_NON-POL: CAP, CER, 22UF, 20%, X5R, 25V, 0805; Cy_part#: 510-60564-01; Mfr_Name: Murata Electronics; Mfr_Part#: GRM21BR61E226ME44L; Sub_Asm: Power In; Tolerance: 20%; VOLTAGE: 25V
C135 = CAPACITOR_NON-POL: CAP, CER, 22UF, 20%, X5R, 25V, 0805; Asm_Instruction: No Load; Mfr_Name: Yageo; Mfr_Part#: CC0805MKX5R8BB226; Sub_Asm: Power In; Tolerance: 20%; VOLTAGE: 25V
C136 C137 = CAPACITOR_NON-POL: CAP, CER, 10uF, 20%, 25V, X5R, 0603; Cy_Part#: 510-60180-01; Mfr_Name: Murata Electronics; Mfr_Part#: GRM188R61E106MA73D; Sub_Asm: Power In; Tolerance: 20%; VOLTAGE: 25V
C138 = CAPACITOR_NON-POL: CAP, CER, 10uF, 10%, 25V, X5R, 0805; Asm_Instruction: No Load; Mfr_Name: TDK Corporation; Mfr_Part#: C2012X5R1E106K085AC; Sub_Asm: Power In; Tolerance: 10%; VOLTAGE: 25V
C139 = CAPACITOR_NON-POL: CAP, CER, 10uF, 10%, 25V, X5R, 0805; Cy_Part#: 510-60052-01; Mfr_Name: Murata Electronics; Mfr_Part#: GRM21BR61E106KA73L; Sub_Asm: Power In; Tolerance: 10%; VOLTAGE: 25V
C140 C141 C143 = CAPACITOR_NON-POL: CAP, CER, 0.1UF, 10%, X5R, 50V, 0402; Cy_Part#: 510-60330-01; Mfr_Name: Murata Electronics; Mfr_Part#: GRM155R61H104KE14D; Sub_Asm: Power In; Tolerance: 10%; VOLTAGE: 50V
C142 = CAPACITOR_NON-POL: CAP, CER, 22PF, 2%, COG, 50V, 0402; Asm_Instruction: No Load; Cy_part#: 510-60318-01; Mfr_Name: TDK Corporation; Mfr_Part#: C1005C0G1H220G050BA; Sub_Asm: Power In; Tolerance: 2%; VOLTAGE: 50V
C148 = CAPACITOR_NON-POL: CAP, CER, 1UF, 10%, 25V, X5R, 0402; Cy_Part#: 510-60560-01; Mfr_Name: Murata Electronics; Mfr_Part#: GRM155R61E105KA12D; Sub_Asm: Power In; Tolerance: 10%; VOLTAGE: 25V
D3-D7 = DIO_STKY_PMEG3020_0: DIODE SCHOTTKY 30V 2A SOD128; Cy_part#: 530-60131-01; Mfr_Name: NXP Semiconductors; Mfr_Part#: PMEG3020BEP,115; Sub_Asm: Power In
J9 = Terminal_Block: CONN, TERM, BLOCK, 2.54MM, 2POS, PCB; Cy_part#: 720-60267-01; HARD_LOCATION: YES; Mfr_Name: On Shore Technology Inc.; Sub_Asm: Power In
J10 = CONN_USB_TYPE_C: CONN, RCPT, USB C, TOP, MNT, HYBRID; Cy_part#: 720-60341-01; HARD_LOCATION: YES; Mfr_Name: JAE Electronics; Mfr_Part#: DX07S024XJ1R1100; Sub_Asm: Power In
L10 = INDUCTOR: IND, 1.5UH, 5.2A, 20% SMD; Mfr_Name: Pulse Electronics Corporation; Mfr_Part#: PA4332.152NLT; ROOM: room1; Sub_Asm: Power In; Tolerance: 20%
R69 R76 R80 R103 R121 R167 R170 R197 = RESISTOR: RES, 100K OHM, 5%, 200PPM, 1/10W, 0402; Mfr_Name: Panasonic; Mfr_Part#: ERJ-2GEJ104X; Sub_Asm: Power In; Tolerance: 5%
R163 = RESISTOR: RES, 10K OHM, 5%, 1/10W, 0402, SMD; Asm_Instruction: No Load; Mfr_Name: Panasonic; Mfr_Part#: ERJ-2GEJ103X; ROOM: room1; Sub_Asm: Power In; Tolerance: 5%
R164 R168 = RESISTOR: RES, 10K OHM, 5%, 1/10W, 0402, SMD; Mfr_Name: Panasonic; Mfr_Part#: ERJ-2GEJ103X; ROOM: room1; Sub_Asm: Power In; Tolerance: 5%
R165 = RESISTOR: RES SMD 560K OHM 1% 1/16W 0402; Cy_part#: 500-60007-01; Mfr_Name: Yageo; Mfr_Part#: RC0402FR-07560KL; ROOM: room1; Sub_Asm: Power In; Tolerance: 1%
R169 R171 = RESISTOR: RES SMD 100K OHM 1% 1/16W 0402; Mfr_Name: Yageo; Mfr_Part#: RC0402FR-07100KL; ROOM: room1; Sub_Asm: Power In; Tolerance: 1%
TP8 = TEST_POINT: TEST POINT PC MINI .040"D BLACK; CLASS: DISCRETE; Mfr_Name: Keystone Electronics; Mfr_Part#: 5001; ROHS: YES
TP12 = TEST_POINT: TEST POINT PC MINI .040"D BLACK; Asm_Instruction: No Load; CLASS: DISCRETE; Mfr_Name: Keystone Electronics; Mfr_Part#: 5001; ROHS: YES
TP27 = TEST_POINT: TEST POINT PC MINI .040"D RED; Asm_Instruction: No Load; Cy_part#: 711-60001-01; Mfr_Name: Keystone Electronics; Mfr_Part#: 5000; ROHS: YES; Sub_Asm: Power In
TP28 = TEST_POINT: TEST POINT PC MINI .040"D BLACK; Asm_Instruction: No Load; Mfr_Name: Keystone Electronics; Mfr_Part#: 5001; ROHS: YES
TVS2 = DT2636-04S-7: TVS DIODE 5.5VWM 9VC; Mfr_Name: Diodes Inc; Sub_Asm: Power In
TVS3 TVS5 = DIODE_BI-DIR_TRIG: TVS DIODE 12VWM 19VC SOD323; Mfr_Name: ON Semiconductor; Sub_Asm: Power In
U28 U29 = SiP32408_0: IC SW W/CTRL SLEW RATE 4TDFN; Mfr_Name: Vishay Siliconix; Mfr_Part#: SIP32408DNP-T1-GE4
U30 = TPS63000_3: Buck-Boost Regulator, 5V, 2A, VFQFN; Mfr_Name: Texas Instruments; Mfr_Part#: TPS63070RNMT; ROOM: room1; Sub_Asm: Power In
U1 = PSoC6_BLE_Hetero_0: MCU, PSoC 6, Performance, 1024KB, 124B-GA, Dual Core,150MHz; HARD_LOCATION: YES; Mfr_Name: Cypress
R47 R52 R53 R58-R61 R63 = RESISTOR: RES, 560 OHM, 5%, 200PPM, 1/10W, 0603, SMD; Cy_part#: 500-60134-01; Mfr_Name: Panasonic-ECG; Mfr_Part#: ERJ-3GEYJ561V; Tolerance: 5%
R12 R13 R62 R70-R73 R82 R83 R126 R131 R146 R161 R173 R175 R176 R186-R189 = RESISTOR: RES SMD 0.0OHM JUMPER 1/10W 0603; Cy_part#: 500-60108-01; Mfr_Name: Rohm Semiconductor; Mfr_Part#: MCR03EZPJ000
R64 R74 R120 R135 R142 R149 R152 R153 R158 R160 R162 R166 R172 R174 R177-R181 = RESISTOR: RES SMD 0.0OHM JUMPER 1/10W 0603; Asm_Instruction: No Load; Cy_part#: 500-60108-01; Mfr_Name: Rohm Semiconductor; Mfr_Part#: MCR03EZPJ000
R113-R117 R133 = RESISTOR: RES, 0 OHM, 1/10W, 0402, SMD; Asm_Instruction: No Load; Mfr_Name: Panasonic; Mfr_Part#: ERJ-2GE0R00X
C27 = CAP: CAP CER 2200PF 50V NP0 0805; Cy_part#: 510-60190-01; Mfr_Name: Murata Electronics; Mfr_Part#: GRM2165C1H222JA01D; Mfr_Part_Number: GRM2165C1H222JA01D; ROHS: YES; Tolerance: 5%; VOLTAGE: 50V
C29 = CAP: CAP CER 10000PF 50V NP0 0805; Cy_part#: 510-60133-01; Mfr_Name: Murata Electronics; Mfr_Part#: GRM2195C1H103JA01D; Mfr_Part_Number: GRM2195C1H103JA01D; ROHS: YES; Tolerance: 5%; VOLTAGE: 50V
C31 C33 = CAP: CAP CER 470PF 50V 5% NP0 0805; Cy_part#: 510-60417-01; Mfr_Name: Murata Electronics; Mfr_Part#: GRM2165C1H471JA01D; ROHS: YES; Tolerance: 5%; VOLTAGE: 50V
C61 C62 C75 C81 C94 C109 = CAPACITOR_NON-POL: CAP, CER, 1UF, 10%, 25V, X5R, 0402; Cy_Part#: 510-60560-01; Mfr_Name: Murata Electronics; Mfr_Part#: GRM155R61E105KA12D; Tolerance: 10%; VOLTAGE: 25V
C85 C86 = CAP_NP: CAP, CER, 22PF, 5%, COG, 50V, 0402; Cy_part#: 510-60716-01; Mfr_Name: Yageo; Mfr_Part#: CC0402JRNPO9BN220; Mfr_Part_Number: CC0402JRNPO9BN220; ROHS: YES; Tolerance: 5%; VOLTAGE: 50V
C96 C99 = CAP: CAP CER 12PF 50V NP0 0402; Cy_part#: 510-60107-01; MFR_NAME: Murata Electronics; MFR_PART_NUMBER: GRM1555C1H120JA01D; Mfr_Part#: GRM1555C1H120JA01D; Package: SMD; Terasic_Prt: MCC-3041-XXX; Type: Capacitor
C103 = CAP_POL: CAP, 330MF, -20% +80%, 3.3V, SMD; Asm_Instruction: No Load; Cy_part#: 510-60556-01; Mfr_Name: Elna America; Mfr_Part#: DSK-3R3H334T-HL; Sub_Asm: Power In; Tolerance: -20%, +80%; VOLTAGE: 3.3V
C17 C95 C108 C110 C121 = CAPACITOR_NON-POL: CAP, CER, 0.1UF, 10%, X5R, 50V, 0402; Cy_Part#: 510-60330-01; Mfr_Name: Murata Electronics; Mfr_Part#: GRM155R61H104KE14D; Tolerance: 10%; VOLTAGE: 50V
CAP_SH1 = CAP_SHIELD: CapSense, Shield, Hash pattern; Asm_Instruction: No Load; Cy_Part#: -NA-; Mfr_Name: -NA-; Mfr_Part#: -NA-
CSB1 CSB2 = Cap_Button_Circle_Mutual: CapSense, Button, Cricle, Mutual; Asm_Instruction: No Load; Cy_part#: -NA-; HARD_LOCATION: YES; Mfr_Name: -NA-; Mfr_Part#: -NA-
CSS1 = CapSense_Slider_5_Seg_Mutual_2: CapSense, Slider, 5 Segment, Mutual; Asm_Instruction: No Load; Cy_part#: -NA-; Mfr_Name: -NA-; Mfr_Part#: -NA-
J13 = TEST_POINT_0: CONN RCPT 1POS .100" SNGL HORZ; Cy_part#: 720-60026-01; HARD_LOCATION: YES; Mfr_Name: Samtec Inc; Mfr_Part#: BCS-101-L-S-HE
LED5 = RGB_LED: LED, 621nm/525nm/465nm, RED/GREEN/BLUE, SMT; HARD_LOCATION: YES; Mfr_Name: Kingbright; Mfr_Part#: AAA3528LSEEZGKQBKS
LED8 = LED_0: LED ORANGE CLEAR 0805 SMD; HARD_LOCATION: YES; Mfr_Name: Kingbright; Mfr_Part#: APT2012LSECK/J4-PRV
LED9 = LED_0: LED RED CLEAR 0805 SMD; HARD_LOCATION: YES; Mfr_Name: Lite-On Inc; Mfr_Part#: LTST-C170CKT
R8 = RESISTOR: RES, 330 OHM, 5%, 1/10W, 0402, SMD; Cy_Part#: 500-60306-01; Mfr_Name: Panasonic; Mfr_Part#: ERJ-2GEJ331X; Tolerance: 5%
R18 = RESISTOR: RES, 750 OHM, 5%, 1/10W, 0402, SMD; Mfr_Name: Yageo; Mfr_Part#: RC0402JR-07750RL; Tolerance: 5%
R19 = RESISTOR: RES, 270 OHM, 5%, 1/10W, 0402, SMD; Cy_Part#: 500-60306-01; Mfr_Name: Panasonic; Mfr_Part#: ERJ-2GEJ271X; Tolerance: 5%
R27 = RESISTOR: RES, 1K OHM, 5%, 1/10W, 0402, SMD; Cy_Part#: 500-60306-01; Mfr_Name: Panasonic; Mfr_Part#: ERJ-2GEJ102X; Tolerance: 5%
R31 = RESISTOR: RES, 100 OHM, 5%, 1/10W, 0402, SMD; Mfr_Name: Panasonic; Mfr_Part#: ERJ-2GEJ101X; Tolerance: 5%
R44 R65 = 330_ohm_5%_0805_0: RES SMD 0.0OHM JUMPER 1/10W 0603; Cy_part#: 500-60108-01; Mfr_Name: Rohm Semiconductor; Mfr_Part#: MCR03EZPJ000
R45 R66 R145 = 330_ohm_5%_0805_0: RES SMD 0.0OHM JUMPER 1/10W 0603; Asm_Instruction: No Load; Cy_part#: 500-60108-01; Mfr_Name: Rohm Semiconductor; Mfr_Part#: MCR03EZPJ000
R67 R91 = RESISTOR: RES, 10K OHM, 5%, 1/10W, 0402, SMD; Mfr_Name: Panasonic; Mfr_Part#: ERJ-2GEJ103X; Tolerance: 5%
R17 R38 R39 R68 = RESISTOR: RES, 10K OHM, 5%, 1/10W, 0402, SMD; Asm_Instruction: No Load; Mfr_Name: Panasonic; Mfr_Part#: ERJ-2GEJ103X; Tolerance: 5%
R86 = RESISTOR: RES SMD 1M OHM 1% 1/16W 0402; Mfr_Name: Yageo; Mfr_Part#: RC0402FR-071ML; Sub_Asm: Power In; Tolerance: 5%
R147 = RESISTOR: RES, 4.7K OHM, 5%, 100PPM, 1/16W, 0402; Cy_part#: 500-60095-01; Mfr_Name: Yageo; Mfr_Part#: RC0402JR-074K7L; Tolerance: 5%
SW1 SW2 = SW_KEY-SPST_1: SWITCH TACTILE SPST-NO 0.05A 12V; HARD_LOCATION: YES; Mfr_Name: Panasonic Electronic Components
SW7 = SW_DPDT_JS202011CQN_1: SWITCH SLIDE DPDT 300MA 6V; HARD_LOCATION: YES; Mfr_Name: C&K Components; Sub_Asm: Power In
U12 U20 = AP22802_5: IC BUFF/DVR TRI-ST 1BIT SOT25; Mfr_Name: Diodes Incorporated
U18 = AP22802_3: IC REG LDO 1.8V 0.2A SMV; Mfr_Name: Toshiba Semiconductor
Y1 = CRYSTAL: CRYSTAL 32.768kHz 12.5pF 20ppm; Cy_part#: 542-60016-01; Mfr_Name: ECS Inc; Mfr_Part#: ECS-.327-12.5-34B-TR; Mfr_Part_Number: ECS-.327-12.5-34B-TR; ROHS: YES
Y2 = CRYSTAL: CRYSTAL 17.20320MHz 18PF SMD; Mfr_Name: Abracon LLC; Mfr_Part#: HC49/4HSMX
C111 C112 = CAPACITOR_NON-POL: CAP CER 22UF 6.3V X5R 0603; Cy_Part#: 510-60365-01; Mfr_Name: Murata; Mfr_Part#: GRM188R60J226MEA0J; Sub_Asm: Buck; VOLTAGE: 6.3V
J1 J4 = CON8: CONN, FEMALE, 2.54mm, 8POS, DL, GOLD, TH; Cy_part#: 710-60025-01; HARD_LOCATION: YES; Mfr_Name: Protectron Electromech; Mfr_Part#: P9401-08-21
J2 = CONN_8: CONN, FEMALE, 2.54mm, 20POS, DL, GOLD, TH; HARD_LOCATION: YES; Mfr_Name: Sullins Connector Solutions; Mfr_Part#: PPPC102LFBN-RC
J3 = CON10: CONN, FEMALE, 2.54mm, 10POS, DL, GOLD, TH; HARD_LOCATION: YES; Mfr_Name: Sullins Connector Solutions; Mfr_Part#: PPPC101LFBN-RC
J5 = RECPT_4X2_100MIL_3: HEADER 6POS.1" DL GOLD; Asm_Instruction: No Load; HARD_LOCATION: YES; Mfr_Name: Sullins Connector Solutions; Mfr_Part#: PPPC032LFBN-RC
J14 = CON6_1: CONN FEMALE 6POS .100" R/A GOLD; Asm_Instruction: No Load; HARD_LOCATION: YES; Mfr_Name: Sullins Connector Solutions; Mfr_Part#: PPPC061LGBN-RC
J18 J20 = HEADER_8: HDR, MALE, 2.54mm, 8POS, DL, GOLD, TH; Cy_part#: 720-60391-01; HARD_LOCATION: YES; Mfr_Name: Protectron Electromech; Mfr_Part#: P9101-08-12-1
J19 = HEADER_10: HDR, MALE, 2.54mm, 10POS, DL, GOLD, TH; HARD_LOCATION: YES; Mfr_Name: Sullins Connector Solutions; Mfr_Part#: PBC10SAAN
J21 = RECPT_4X2_100MIL_6: HEADER 8POS.1" DL GOLD; Asm_Instruction: No Load; Cy_part#: 720-60283-01; HARD_LOCATION: YES; Mfr_Name: Sullins Connector Solutions; Mfr_Part#: PPPC042LFBN-RC
J26 = 2_PIN_Header: Asm_Instruction: No Load; Mfr_Name: 3M; Mfr_Part#: 961102-6404-AR
R134 = RESISTOR: RES, 10K OHM, 5%, 1/10W, 0402, SMD; Mfr_Name: Panasonic; Mfr_Part#: ERJ-2GEJ103X; TOLERANCE: 5%
U4 = S25FL512SAGBHIA13_1: IC FLASH 512MBIT 133MHZ 24BGA; HARD_LOCATION: YES; Mfr_Name: Cypress
U5 = ULE_FRAM: IC FRAM 1MBIT 40MHZ 8SOIC; HARD_LOCATION: YES; Mfr_Name: Cypress Semiconductor; Mfr_Part#: CY15B104QSN-108SXI
U24 = SIP32402ADNP_1: IC SW W/CTRL SLEW RATE 4TDFN; Mfr_Name: Vishay Siliconix; Mfr_Part#: SIP32402ADNP-T1GE4
C5 C11 C13 C50 C53 C57 C76 C82 = CAPACITOR_NON-POL: CAP, CER, 0.1UF, 10%, X5R, 50V, 0402; Cy_part#: 510-60330-01; Mfr_Name: Murata Electronics; Mfr_Part#: GRM155R61H104KE14D; Tolerance: 10%; VOLTAGE: 50V
C58 C65 = CAPACITOR_NON-POL: CAP, CER, 0.01uF, 10%, X7R, 50V, 0402; Cy_part#: 510-60089-01; Mfr_Name: Murata Electronics; Mfr_Part#: GRM155R71H103KA88D; Mfr_Part_Number: GRM155R71H103KA88D; Tolerance: 10%; VOLTAGE: 50V
C66 = CAPACITOR_NON-POL: CAP, CER, 10uF, 10%, 25V, X5R, 0805; Cy_Part#: 510-60052-01; Mfr_Name: Murata Electronics; Mfr_Part#: GRM21BR61E106KA73L; Mfr_Part_Number: C2012X5R1E106K085AC; Tolerance: 10%; VOLTAGE: 25V
J27 = USB_A_RECEPTACLE: CONN, RCPT, USB, R/A, TYPE A, 4POS; Cy_part#: 720-60146-01; Mfr_Name: Molex; Mfr_Part#: 676433911
J28 = CONN_USB_TYPE_C: CONN, RCPT, USB C, TOP, MNT, HYBRID; Cy_part#: 720-60341-01; Mfr_Name: JAE Electronics; Mfr_Part#: DX07S024XJ1R1100; Sub_Asm: Power In
R78 R79 R90 R97 R101 R107 = RESISTOR: RES, 100K OHM, 5%, 200PPM, 1/10W, 0402; Mfr_Name: Panasonic; Mfr_Part#: ERJ-2GEJ104X; Tolerance: 5%
R198 R199 = RESISTOR: RES, 5.1K OHM, 5%, 100PPM, 1/16W, 0402; Cy_part#: 500-60095-01; Mfr_Name: Yageo; Mfr_Part#: RC0402JR-075K1L; Sub_Asm: KitProg; Tolerance: 5%
TVS1 = TVS_5V_SOD-323_0: DIO, TVS, UNIDIR, 350W, 5V, SOD-323; Cy_part#: 530-60056-01; Mfr_Name: Dioded Inc.
U14 = 74LVC1G07: IC BUFF OPEN DRAIN N-INV 5TSSOP; Mfr_Name: NXP Semiconductors
U15 = AP22802: IC PWR SW USB 1CH 0.5A SOT-25-5; Mfr_Name: Diodes Incorporated
U16 = NLAS7242: C USB SWITCH DPST 10UQFN; Mfr_Name: ON Semiconductor
U22 = AP22802_2: IC BUFF/DVR TRI-ST 1BIT SOT25; Mfr_Name: Diodes Incorporated
ANT1 = Wiggle_Antenna_7: Antennas 2450+/-50MHz 2.9GHz Fc 2dBi; Cy_Part_Number: 753-60005-01; Cy_part#: 753-60005-01; Mfr_Name: Walsin
C1 C2 = CAP: CAP CER 1.2PF 50V NP0 0402; Asm_Instruction: No Load; Cy_part#: 510-60250-01; Mfr_Name: Johanson Technology Inc.; Mfr_Part#: 500R07S1R2BV4T; VOLTAGE: 50V
C4 = CAP: CAP CER 10PF 50V NP0 0402; Cy_Part_Number: 510-60722-01; Cy_part#: 510-60722-01; Mfr_Name: Murata Electronics; Mfr_Part#: GRM1555C1H100GA01D; VOLTAGE: 50V
C7 C12 = CAP: CAP, CER, 4.7uF, 10%, 16V, X5R, 0603; Cy_Part#: 510-60058-01; Loading: Yes; Mfr_Name: Murata Electronic; Mfr_Part#: GRM188R61C475KAAJD; Mfr_Part_Number: GRM188R61C475KAAJD; Tolerance: 10%; VOLTAGE: 16V
C54 = CAPACITOR_NON-POL: CAP CER 2.2UF 10V X5R 0402; Cy_Part#: 510-60376-01; Mfr_Name: Murata Electronics; Mfr_Part#: GRM155R61A225ME95D; VOLTAGE: 10V
J25 = RECPT_4X2_100MIL_2: CONN, BOX, HEADER, 0.050", 10POS; Asm_Instruction: No Load; Cy_part#: 720-60230-01; Mfr_Name: Samtec; Mfr_Part#: FTSH-105-01-L-DV-K; Sub_Asm: KitProg
J29 = CONN_MMCX_0: CONN SWD JACK STR 50 OHM SMD; Asm_Instruction: No Load; Mfr_Name: Murata Electronics North America
L1 L11 L12 = INDUCTOR: FIXED IND 6.8NH 250MA 320 MOHM; Mfr_Name: Johanson Technology Inc.; Mfr_Part#: L-07C6N8JV6T; ROHS: YES
L2 = INDUCTOR: FIXED IND 2.2UH 1.2A 138 MOHM; Mfr_Name: Murata Electronics; Mfr_Part#: LQM2MPN2R2MG0L
L3 L7 = INDUCTOR_FERRITE: FERRITE BEAD 1 KOHM 0805; CLASS: DISCRETE; Mfr_Name: Murata Electronics; Mfr_Part#: BLM21AG102SN1D; PART_TYPE: FERRITE; ROHS: YES
L13 = INDUCTOR: FIXED IND 6.8NH 250MA 320 MOHM; Asm_Instruction: No Load; Mfr_Name: Johanson Technology Inc.; Mfr_Part#: L-07C6N8JV6T; ROHS: YES
R20 R89 = RESISTOR: RES, 10K OHM, 5%, 1/10W, 0402, SMD; Asm_Instruction: No Load; Mfr_Name: Panasonic; Mfr_Part#: ERJ-2GEJ103X; TOLERANCE: 5%
R21 = RESISTOR: RES, 49.9K OHM, 1%, 100PPM, 1/10W, 0402, SMD; Asm_Instruction: No Load; Cy_part#: 500-60149-01; Mfr_Name: Panasonic; Mfr_Part#: ERJ-2RKF4992X; Sub_Asm: Buck; Tolerance: 1%
R22-R25 R96 = RESISTOR: RES, 49.9K OHM, 1%, 100PPM, 1/10W, 0402, SMD; Cy_part#: 500-60149-01; Mfr_Name: Panasonic; Mfr_Part#: ERJ-2RKF4992X; Sub_Asm: Buck; Tolerance: 1%
R28 R32 R36 R122 R128 R132 = RESISTOR: RES SMD 33 OHM 1% 1/16W 0402; Cy_part#: TBD; Mfr_Name: 'YAGEO; Mfr_Part#: RC0402FR-0733RL; Mfr_Part_Number: RC0402FR-0733RL; Tolerance: 1%
R99 R108-R112 R200-R203 = RESISTOR: RES, 0 OHM, 1/10W, 0402, SMD; Mfr_Name: Panasonic; Mfr_Part#: ERJ-2GE0R00X
TP1 TP4 TP13-TP15 TP17 TP18 TP22-TP24 TP31 TP33-TP35 TP37 TP40-TP43 = TEST_POINT: TESTPOINT, SMD, 40MILS, ROUND; Asm_Instruction: No Load; Mfr_Name: -NA-; Mfr_Part#: -NA-
TP11 TP16 TP19 = TEST_POINT: TEST POINT PC MINI .040"D RED; Asm_Instruction: No Load; Cy_part#: 711-60001-01; Mfr_Name: Keystone Electronics; Mfr_Part#: 5000
U6 = CYPD2122-24LQXIT_6: WI-FI-B/G/N AND BLE DEVELOPMENT; Mfr_Name: Murata Electronics North America
U11 = SG-210STF_32.7680ML: OSC XO 32.768KHZ CMOS SMD; Mfr_Name: EPSON
ACC6 ACC7 ACC10 ACC11 = SJ61A4: HW, BUMPON, CYLIN, 0.375", DIA, BLK; Cy_part#: 700-60093-01; Mfr_Name: 3M; Sub_Allowed: NO
ACC8 = Acrylic_Overlay: HW, OVERLAY, CY8CKIT-062-BLE, Acrylic, 40mmx34mmx1mm; Cy_part#: 700-60132-01; Mfr_Name: Cypress Approved CM; Sub_Allowed: NO
ACC9 = Jumper_Shunt: HW, CONN, Rectangular, MINI JUMPER, 6mm, CLOSE TYPE, BLACK, NICKEL; Cy_part#: 700-60076-01; Mfr_Name: Sullins Connector Solutions; Sub_Allowed: NO
ACC12 = LBL_PCA_Label: LBL, PCA Label, Vendor Code, Datecode, Serial Number (YYWWVVXXXXX); Cy_part#: 899-60120-01; Mfr_Name: JETech; Mfr_Part#: 899-60120-01; Mfr_Part_Number: 899-60120-01; Sub_Allowed: NO
ACC13 = LBL_QR_Code: LBL, QR Code 10mm X 10mm, CY8CKIT-062-BLE; Mfr_Name: JETech; Mfr_Part#: 899-60120-01; Mfr_Part_Number: 899-60120-01; Sub_Allowed: NO
ACC14 ACC15 = 22_AWG_Bus_Bar_Wire: WIRE, WIRE BUS BAR 1000' LONG, THICKNESS 22 AWG; Cy_part#: 751-60031-01; Mfr_Name: Alpha Wire; Sub_Allowed: NO

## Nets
5V_OUT: C133.1 C134.1 C135.1 C136.1 C141.2 C142.1 D5.A(ANODE) R165.2 R171.1 U29.1(IN) U29.3(EN) U30.7(VOUT1) U30.8(VOUT2) ; also on sheet 7
GND: C1.1 C2.1 C5.2 C7.2 C11.2 C12.2 C13.2 C17.2 C27.1 C29.2 C31.2 C33.1 C48.2 C50.2 C51.2 C53.2 C54.2 C57.2 C58.2 C59.2 C60.2 C61.1 C62.1 C65.2 C66.2 C75.2 C76.1 C81.1 C82.1 C85.2 C86.2 C89.2 C92.2 C94.2 C95.2 C96.2 C99.2 C103.2 C108.2 C109.2 C110.2 C111.2 C112.2 C121.2 C133.2 C134.2 C135.2 C136.2 C137.2 C138.2 C139.2 C140.1 C141.1 C143.1 C148.1 J1.2 J1.3 J2.14 J3.7 J5.6 J9.1 J10.A1(GND_1) J10.A12(GND_2) J10.B1(GND_3) J10.B12(GND_4) J14.5 J19.7 J21.7 J25.2 J25.4 J25.6 J25.8 J25.10 J27.4(GND) J28.A1(GND_1) J28.A12(GND_2) J28.B1(GND_3) J28.B12(GND_4) J29.G1 J29.G2 J29.G3 J29.G4 L11.2 L12.2 R44.2 R65.2 R68.1 R69.2 R76.1 R78.2 R79.2 R86.1 R90.1 R101.1 R107.2 R121.2 R167.1 R168.1 R169.1 R170.1 R198.1 R199.1 SW1.A(2) TP8.1 TP12.1 TP28.1 TVS2.3 TVS5.1 U4.B3(VSS) U5.4(VSS) U6.1(GND1) U6.12(GND) U6.19(GND) U6.21(GND) U6.29(GND) U6.32(GND(SR_PVSS)) U6.33(GND(SR_PVSS)) U6.35(GND) U6.40(GND40) U6.42(GND42) U6.43(GND43) U6.44(GND44) U6.45(GND45) U6.46(GND46) U11.2(GND) U12.3(GND) U14.3(GND) U15.2(GND) U16.3(GND) U16.8(~{OE}) U18.2(GND) U20.3(GND) U22.3(GND) U24.2(GND) U24.H(PAD) U28.2(GND) U28.H(PAD) U29.2(GND) U29.H(PAD) U30.4(GND) U30.6(FB2) U30.10(PGND) U30.15(VSEL) ; also on sheet 3 4 5 6 7 8
GND_EARTH1: C48.1 J28.SH1 J28.SH2 J28.SH3 J28.SH4 R69.1 TVS1.A
GND_EARTH2: C58.1 J27.5(S1) J27.6(S2) R78.1
GND_EARTH3: C92.1 J10.SH1 J10.SH2 J10.SH3 J10.SH4 R121.1 TVS3.1
VBUS_DEV: C51.1 D3.A(ANODE) J28.A4(VBUS_1) J28.A9(VBUS_2) J28.B4(VBUS_3) J28.B9(VBUS_4) R101.2 TVS1.K U22.1(OE) U22.2(IN)
VBUS_HOST: C57.1 C66.1 J27.1(VBUS) U15.1(OUT)
VBUS_TC: C89.1 D6.A(ANODE) J10.A4(VBUS_1) J10.A9(VBUS_2) J10.B4(VBUS_3) J10.B9(VBUS_4) R167.2 TVS3.2 ; also on sheet 4 6 7
VCC_1V8: C76.2 C81.2 R103.2 U14.5(VCC) U18.5(OUT) U20.5(VCC)
VCC_3V3: C13.1 C65.1 C109.1 C110.1 C111.1 L3.1 U4.B4(VCC) U16.9(VCC) U24.4(EN) U28.1(IN) U28.3(EN) ; also on sheet 3 8
VCC_5V: C61.2 C62.2 D3.K(CATHODE) D4.K(CATHODE) D5.K(CATHODE) R80.2 R97.1 R197.2 TP27.1 U12.5(VCC) U15.5(IN) U18.1(VIN) U18.3(CONTROL) ; also on sheet 3 4 6 8
VCC_IN: C137.1 C138.1 C139.1 C140.2 D6.K(CATHODE) D7.K(CATHODE) R163.2 R164.2 U30.12(VIN1) U30.13(VIN2)
VCC_IO_FLASH: C94.1 C95.1 R134.1 U4.E4(VIO/RFU) U24.1(OUT)
VDDD: R91.1 R147.1 SW7.1 ; also on sheet 8
VIN: C148.2 D7.A(ANODE) J1.1 J9.2 R170.2 TVS5.2 ; also on sheet 6 7
ANT: C4.2 L11.1 U6.41(ANT)
BT_DEV_WAKE_P4_0: TP35.1 U1.L7(P4_0) U6.39(BT_DEV_WAKE)
BT_GPIO_3: TP22.1 U6.6(BT_GPIO_3)
BT_GPIO_4: TP23.1 U6.7(BT_GPIO_4)
BT_GPIO_5: TP17.1 U6.13(BT_GPIO_5)
BT_HOST_WAKE_P3_5: TP31.1 U1.N6(P3_5) U6.38(BT_HOST_WAKE)
BT_I2S_DO: TP18.1 U6.16(BT_I2S_dO)
BT_PCM_CLK: TP15.1 U6.11(BT_PCM_CLK)
BT_PCM_IN: TP13.1 U6.9(BT_PCM_IN)
BT_PCM_OUT: TP14.1 U6.10(BT_PCM_OUT)
BT_PCM_SYNC: TP24.1 U6.8(BT_PCM_SYNC)
BT_REG_ON_P3_4: TP37.1 U1.M6(P3_4) U6.14(BT_REG_ON)
BT_UART_CTS: R202.2 TP42.1 U6.4(BT_UART_CTS)
BT_UART_RTS: R203.2 TP43.1 U6.5(BT_UART_RTS)
BT_UART_RXD: R200.2 TP40.1 U6.2(BT_UART_RXD)
BT_UART_TXD: R201.2 TP41.1 U6.3(BT_UART_TXD)
CAP_BUT0_P8_1: CSB1.3 R61.1
CAP_BUT1_P8_2: CSB2.3 R60.1
CAP_PROX_P8_0: J13.1 J13.2 R63.1 R64.1
CAP_SEG0_P8_3: CSS1.1(0) R53.1
CAP_SEG1_P8_4: CSS1.2(1) R52.1
CAP_SEG2_P8_5: CSS1.3(2) R47.1
CAP_SEG3_P8_6: CSS1.4(3) R58.1
CAP_SEG4_P8_7: CSS1.5(4) R59.1
CAP_TX_P1_0: CSB1.1 CSB1.2 CSB2.1 CSB2.2 CSS1.6(5) R62.2
CC1: C60.1 J10.A5(CC1) TVS2.1 ; also on sheet 6
CC2: C59.1 J10.B5(CC2) TVS2.2 ; also on sheet 6
DEV_USB_DM: J28.A7(DN1) J28.B7(DN2) U16.4(HSD1-)
DEV_USB_DP: J28.A6(DP1) J28.B6(DP2) U16.5(HDS1+)
ECO_P12_6: C99.1 R131.2 Y2.1
ECO_P12_7: C96.1 R126.2 Y2.2
FLASH_CS_P11_2: R134.2 R176.2 U4.C2(~{CS})
FRAM_CS_P11_0: R39.2 R173.2 U5.1(~{CS})
FRAM_VDD: C17.1 J26.1 R13.2 R17.2 R38.2 R39.1 U5.8(VDD)
HOST_USB_DM: J27.2(D-) U16.6(HSD2-)
HOST_USB_DP: J27.3(D+) U16.7(HSD2+)
J1_3V3: J1.5 U28.4(OUT)
J1_5V0: J1.4 U29.4(OUT)
J2_P9_3: J2.8 R162.2
J18_P7_0: J18.6 R181.2
J18_P7_3: J18.5 R146.1
J18_P7_4: J18.4 R178.2
J18_P7_5: J18.3 R179.2
J18_P7_6: J18.2 R180.2
J18_P7_7: J18.1 R142.2
J18_P11_0: J18.8 R175.2
J18_P11_2: J18.7 R177.2
J19_P1_0: J19.5 R174.2
J19_P12_4: J19.10 R74.2
J19_P12_5: J19.9 R73.2
J19_P12_6: J19.8 R135.2
J19_P12_7: J19.6 R120.2
J20_P8_0: J20.1 R64.2
J20_P8_1: J20.2 R172.2
J20_P8_2: J20.3 R166.2
J20_P8_3: J20.4 R153.2
J20_P8_4: J20.5 R152.2
J20_P8_5: J20.6 R149.2
J20_P8_6: J20.7 R158.2
J20_P8_7: J20.8 R160.2
KP_PMIC_EN: R197.1 U12.2(IN) ; also on sheet 4
KP_PMIC_EN_OUT: R80.1 SW7.5 U12.4(OUT) ; also on sheet 3
LPO_IN_32KHZ: U6.37(LPO_IN(32KHZ)) U11.3(OUT)
P0_0: C86.1 U1.E3(P0.0) Y1.1
P0_1: C85.1 U1.E2(P0.1) Y1.2
P0_2: J4.8 U1.E1(P0.2)
P0_3: R18.1 U1.F3(P0.3)
P0_4: R67.1 R68.2 R133.1 SW2.B(1) U1.F2(P0.4)
P0_5: U1.G3(P0.5) U20.2(IN)
P1_0: R62.1 R174.1 U1.G2(P1.0)
P1_1: R8.2 U1.G1(P1.1)
P1_2: J19.4 U1.H3(P1.2)
P1_3: J19.3 U1.H2(P1.3)
P1_4: J19.2 U1.H1(P1.4)
P1_5: J19.1 R27.1 U1.J3(P1.5)
P2_0: R122.1 U1.M2(P2_0)
P2_1: R32.1 U1.N2(P2_1)
P2_2: R128.1 U1.L3(P2_2)
P2_3: R132.1 U1.M3(P2_3)
P2_4: R36.1 U1.N3(P2_4)
P2_5: R28.1 U1.N1(P2_5)
P3_0: R201.1 U1.L5(P3_0)
P3_1: R200.1 U1.M5(P3_1)
P3_2: R202.1 U1.N5(P3_2)
P3_3: R203.1 U1.L6(P3_3)
P4_1: J21.1 U1.M7(P4_1)
P5_0: J4.1 U1.N7(P5.0) ; also on sheet 4
P5_1: J4.2 U1.L8(P5.1) ; also on sheet 4
P5_2: J4.3 U1.M8(P5.2) ; also on sheet 5
P5_3: J4.4 U1.N8(P5.3) ; also on sheet 5
P5_4: J4.5 U1.L9(P5.4)
P5_5: J4.6 U1.M9(P5.5)
P5_6: J4.7 U1.N9(P5.6)
P5_7: J21.3 U1.N10(P5.7)
P5LP_SSEL_P12_4: R83.2 ; also on sheet 5
P5LP_USB_DM: J10.A7(DN1) J10.B7(DN2) TVS2.5 ; also on sheet 4
P5LP_USB_DP: J10.A6(DP1) J10.B6(DP2) TVS2.4 ; also on sheet 4
P5LP_VDD: R76.2 U12.1(OE) ; also on sheet 3 4 5
P6_0: J3.10 U1.M10(P6.0) ; also on sheet 4
P6_1: J3.9 U1.L10(P6.1) ; also on sheet 4
P6_2: J2.15 U1.L11(P6.2)
P6_3: J2.17 R145.2 U1.M11(P6.3)
P6_4: U1.N11(P6.4) ; also on sheet 5
P6_5: U1.M12(P6.5) ; also on sheet 5
P6_6: U1.N12(P6.6) ; also on sheet 5
P6_7: U1.M13(P6.7) ; also on sheet 5
P6_PMIC_EN_OUT: R103.1 SW7.7 U20.4(OUT)
P6_VDD: C50.1 C82.2 C108.1 C112.1 J1.7 J14.6 J26.2 L7.1 R12.1 R13.1 U22.5(VCC) U24.3(IN) ; also on sheet 3 4 5 8
P7_0: R181.1 R189.1 U1.L13(P7.0)
P7_1: C33.2 U1.L12(P7.1)
P7_2: C31.1 U1.K13(P7.2)
P7_3: C29.1 R146.2 U1.N13(P7.3)
P7_4: R178.1 R186.1 U1.K11(P7.4)
P7_5: R179.1 R187.1 U1.J13(P7.5)
P7_6: R180.1 R188.1 U1.J12(P7.6)
P7_7: C27.2 R142.1 U1.J11(P7.7)
P8_0: R63.2 U1.H13(P8.0)
P8_1: R61.2 R172.1 U1.H12(P8.1)
P8_2: R60.2 R166.1 U1.H11(P8.2)
P8_3: R53.2 R153.1 U1.G13(P8.3)
P8_4: R52.2 R152.1 U1.G12(P8.4)
P8_5: R47.2 R149.1 U1.G11(P8.5)
P8_6: R58.2 R158.1 U1.F13(P8.6)
P8_7: R59.2 R160.1 U1.F12(P8.7)
P9_0: J2.2 U1.E11(P9.0)
P9_1: J2.4 U1.E12(P9.1)
P9_2: J2.6 U1.E13(P9.2)
P9_3: R161.1 R162.1 U1.F11(P9.3)
P9_4: J2.10 U1.D13(P9.4)
P9_5: J2.12 U1.D12(P9.5)
P9_6: J2.16 U1.D11(P9.6)
P9_7: J2.18 U1.C13(P9.7)
P10_0: J2.1 U1.C12(P10.0)
P10_1: J2.3 U1.A11(P10.1)
P10_2: J2.5 U1.B11(P10.2)
P10_3: J2.7 U1.C11(P10.3)
P10_4: J2.9 U1.A10(P10.4)
P10_5: J2.11 U1.B10(P10.5)
P10_6: J2.13 U1.C10(P10.6)
P10_7: J21.5 U1.A9(P10.7)
P11_0: R173.1 R175.1 U1.B9(P11.0)
P11_1: R19.2 U1.C9(P11.1)
P11_2: R176.1 R177.1 U1.A8(P11.2)
P11_3: R17.1 U1.B8(P11.3) U4.D4(~{HOLD}/IO3) U5.7(~{RESE}T/IO3)
P11_4: R38.1 U1.C8(P11.4) U4.C4(~{WP}/IO2) U5.3(~{WP}/IO2)
P11_5: U1.A7(P11.5) U4.D2(SO/IO1) U5.2(SO/IO1)
P11_6: U1.B7(P11.6) U4.D3(SI/IO0) U5.5(SI/IO0)
P11_7: U1.C7(P11.7) U4.B2(SCK) U5.6(SCK)
P12_0: J3.4 J5.4 J14.2 U1.A6(P12.0) ; also on sheet 5
P12_1: J3.5 J5.1 J14.3 U1.B6(P12.1) ; also on sheet 5
P12_2: J3.6 J5.3 J14.4 U1.C6(P12.2) ; also on sheet 5
P12_3: J3.3 U1.A5(P12.3)
P12_4: R74.1 R83.1 U1.B5(P12.4)
P12_5: R73.1 R82.1 U1.C5(P12.5)
P12_6: R131.1 R135.1 U1.A4(P12.6)
P12_7: R120.1 R126.1 U1.B4(P12.7)
P13_0: J3.1 U1.B1(P13.0)
P13_1: J3.2 U1.A3(P13.1)
P13_2: J21.2 R72.2 U1.B3(P13.2)
P13_3: J21.4 R71.1 U1.B2(P13.3)
P13_4: J21.6 R70.1 U1.C2(P13.4)
P13_5: J21.8 U1.C1(P13.5)
P13_6: J2.19 R45.2 U1.D3(P13.6)
P13_7: J2.20 R31.1 U1.D2(P13.7)
PMIC_EN: SW7.6 ; also on sheet 3
PMOD_SSEL_P12_5: J14.1 R82.2
SDIO_CLK: R108.2 R113.1 U6.20(SDIO_CLK)
SDIO_CMD: R99.2 U6.22(SDIO_CMD)
SDIO_DATA0: R110.2 R115.1 U6.24(SDIO_DATA0)
SDIO_DATA1: R111.2 R116.1 U6.26(SDIO_DATA1)
SDIO_DATA2: R112.2 R117.1 U6.23(SDIO_DATA2)
SDIO_DATA3: R109.2 R114.1 U6.25(SDIO_DATA3)
SHIELD: CAP_SH1.1(SH) R44.1 R45.1 R145.1
SWD_RST_L: J1.6 J5.5 ; also on sheet 5
TRACECLK: R189.2 ; also on sheet 5
TRACEDATA_0: R161.2 ; also on sheet 5
TRACEDATA_1: R188.2 ; also on sheet 5
TRACEDATA_2: R187.2 ; also on sheet 5
TRACEDATA_3: R186.2 ; also on sheet 5
USB_DEV_VBUS_DET: R70.2 R107.1 U22.4(OUT)
USB_DM: U1.L1(USBDM) U16.2(D-)
USB_DP: U1.L2(USBDP) U16.1(D+)
USB_HOST_EN: R72.1 R79.1 R90.2 U14.2(A) U16.10(S)
USB_INT_L: R71.2 R91.2 U15.3(FLG)
VBACKUP: R66.1 R67.2 R86.2 SW7.2 U20.1(OE) ; also on sheet 8
VREF: J3.8 ; also on sheet 8
VTARG_IN: D4.A(ANODE) ; also on sheet 3 5
WL_GPIO_1: R20.1 TP16.1 U6.18(WL_GPIO_1)
WL_GPIO_2: TP11.1 U6.17(WL_GPIO_2)
WL_GPIO_4: TP19.1 U6.15(WL_GPIO_4)
WL_HOST_WAKE_P2_7: R133.2 TP34.1 U1.N4(P2_7) U6.27(WL_HOST_WAKE)
WL_JTAG_TCK: J25.9 R113.2
WL_JTAG_TDI: J25.3 R116.2
WL_JTAG_TDO: J25.5 R117.2
WL_JTAG_TMS: J25.7 R115.2
WL_JTAG_TRSTN: J25.1 R114.2
WL_REG_ON_P2_6: R89.1 TP33.1 U1.M4(P2_6) U6.28(WL_REG_ON)
WL_VBAT: C11.1 C12.1 C53.1 L3.2 TP4.1 U6.30(VBAT) U11.1(~{ST}) U11.4(VCC)
WL_VDDIO: C5.1 C54.1 L7.2 R20.2 R21.1 R22.1 R23.1 R24.1 R25.1 R89.2 R96.1 TP1.1 U6.36(V_O)
XRES_L: C121.1 R147.2 SW1.B(1) U1.F1(XRES) ; also on sheet 5
N17715190: R164.1 U30.14(EN)
N17715216: C143.2 U30.3(VAUX)
N17715264: R171.2 U30.2(PG)
N17715329: L10.1 U30.11(L1)
N17715335: L10.2 U30.9(L2)
N18060252: C142.2 R165.1 R169.2 U30.5(FB)
N18453045: C75.1 R97.2 U14.4(Y) U15.4(EN)
N18482506: R25.2 R32.2 R111.1
N18482508: R24.2 R109.1 R132.2
N18482512: R22.2 R112.1 R128.2
N18482514: R36.2 R96.2 R99.1
N18482516: R21.2 R28.2 R108.1
N18482684: R23.2 R110.1 R122.2
N18528852: L2.1 U6.34(SR_VLX)
N18619822: C2.2 C4.1 L1.2 L12.1 L13.2
N18743253: R163.1 R168.2 U30.1(PS/SYNC)
N18832502: LED5.2 LED8.A(ANODE) LED9.A(ANODE) R12.2
N18832516: LED8.K(CATHODE) R27.2
N18832538: LED9.K(CATHODE) R31.2
N18832599: LED5.4 R19.1
N18832601: LED5.3 R8.1
N18832603: LED5.1 R18.2
N18833732: R65.1 R66.2 SW2.A(2)
N18852351: C7.1 L2.2 U6.31(VIN_LDO)
N18903176: C103.1 SW7.3
N18985234: J28.B5(CC2) R199.2
N18985239: J28.A5(CC1) R198.2
N19031222: ANT1.1 C1.2 L1.1
N19038486: J29.I(IN) L13.1

Not connected (* = marked no-connect by the designer): ANT1 2*; J1 8*; J5 2*; J10 A2(SSTXP1)* A3(SSTXN1)* A8(SBU1)* A10(SSRXN2)* A11(SSRXP2)* B2(SSTXP2)* B3(SSTXN2)* B8(SBU2)* B10(SSRX1N)* B11(SSRXP1)*; J28 A2(SSTXP1)* A3(SSTXN1)* A8(SBU1)* A10(SSRXN2)* A11(SSRXP2)* B2(SSTXP2)* B3(SSTXN2)* B8(SBU2)* B10(SSRX1N)* B11(SSRXP1)*; J29 O(OUT)*; TVS2 6*; U4 A2(NC_1)* A3(NC_2)* A4(~{RESET}/RFU) A5(NC_3)* B1(DNU_1)* B5(NC_4)* C1(DNU_2)* C3(RFU)* C5(NC_5)* D1(DNU_3)* D5(NC_6)* E1(NC_7)* E2(NC_8)* E3(NC_9)* E5(NC_10)*; U14 1(NC)*; U18 4(NC)*

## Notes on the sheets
sheet 9
- PSoC 6 Signals
- Additional Multiplexed Pins
- CapSense Multiplexed Pins
- TRACE Multiplexed Pins
- Note: Option for WLAN to wake PSoC 6 from Hibernate
sheet 10
- CapSense Button
- CMOD, CSH & CINT
- User LEDs
- CINTA
- Optional CSH
  CINTB
- CMOD
- CSH
- CapSense Shield
- CapSense Slider
- Reset Button
- WCO
- CapSense Proximity
- User Button / Hibernate Wakeup
- ECO
- Backup Supply & PMIC Control
- SuperCap
- SW7
- Source
- POS1
- KitProg3 PMIC Control
- POS2
- PSoC 6 PMIC Control
sheet 11
- Arduino & Extended Headers
- PMOD Header
- ICSP Header
- FRAM
- QSPI Flash (SMIF)
sheet 12
- USB Multiplexer
- USB Type-A Receptacle (Host)
- USB Type-C Connector (Device)
- USB Device Port VBUS Detect
- USB Host VBUS Enable
sheet 13
- WiFi Interface with PSoC 6
- WiFi / BT Module
- Optional JTAG Interface
- Antenna with Matching Network
- Supply for WiFi Module
- Testpoints
sheet 14
- Accessories
- Cylindrical Bumper
- Acrylic Overlay
- Jumper Shunt
- Color: Clear, Transparent
- Finish: Matt
- 40 x 34 x
  1mm
- PCBA label
- USB Type-C Connector Brackets
sheet 15
- REVISION HISTORY
- REV
- DESCRIPTION OF CHANGE
- DATE
- 01
- Internal Release
- 2017/03/13
- 02
- Internal Release
- 2017/09/01
- 03
- Initial Release
- 2017/10/20
- 04
- Changed WCO load capacitors C85 and C86
- 2020/01/29
- 05
- Removed C103 (SuperCap) from assembly
- 2023/12/22
sheet 16
- KitProg3 USB Type-C Connector
- 5V Buck-Boost Regulator
- VIN Header
- Power Supply 'OR'ing
- Arduino Header O/P
